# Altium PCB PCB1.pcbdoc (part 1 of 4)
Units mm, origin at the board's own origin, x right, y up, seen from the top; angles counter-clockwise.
Board outline 96.27 x 122.17 mm, 6 copper layers (Top Layer, Inner1, Inner2, Inner3, Inner4, Bottom Layer); 169 components, 166 nets, 787 pads, 477 vias.
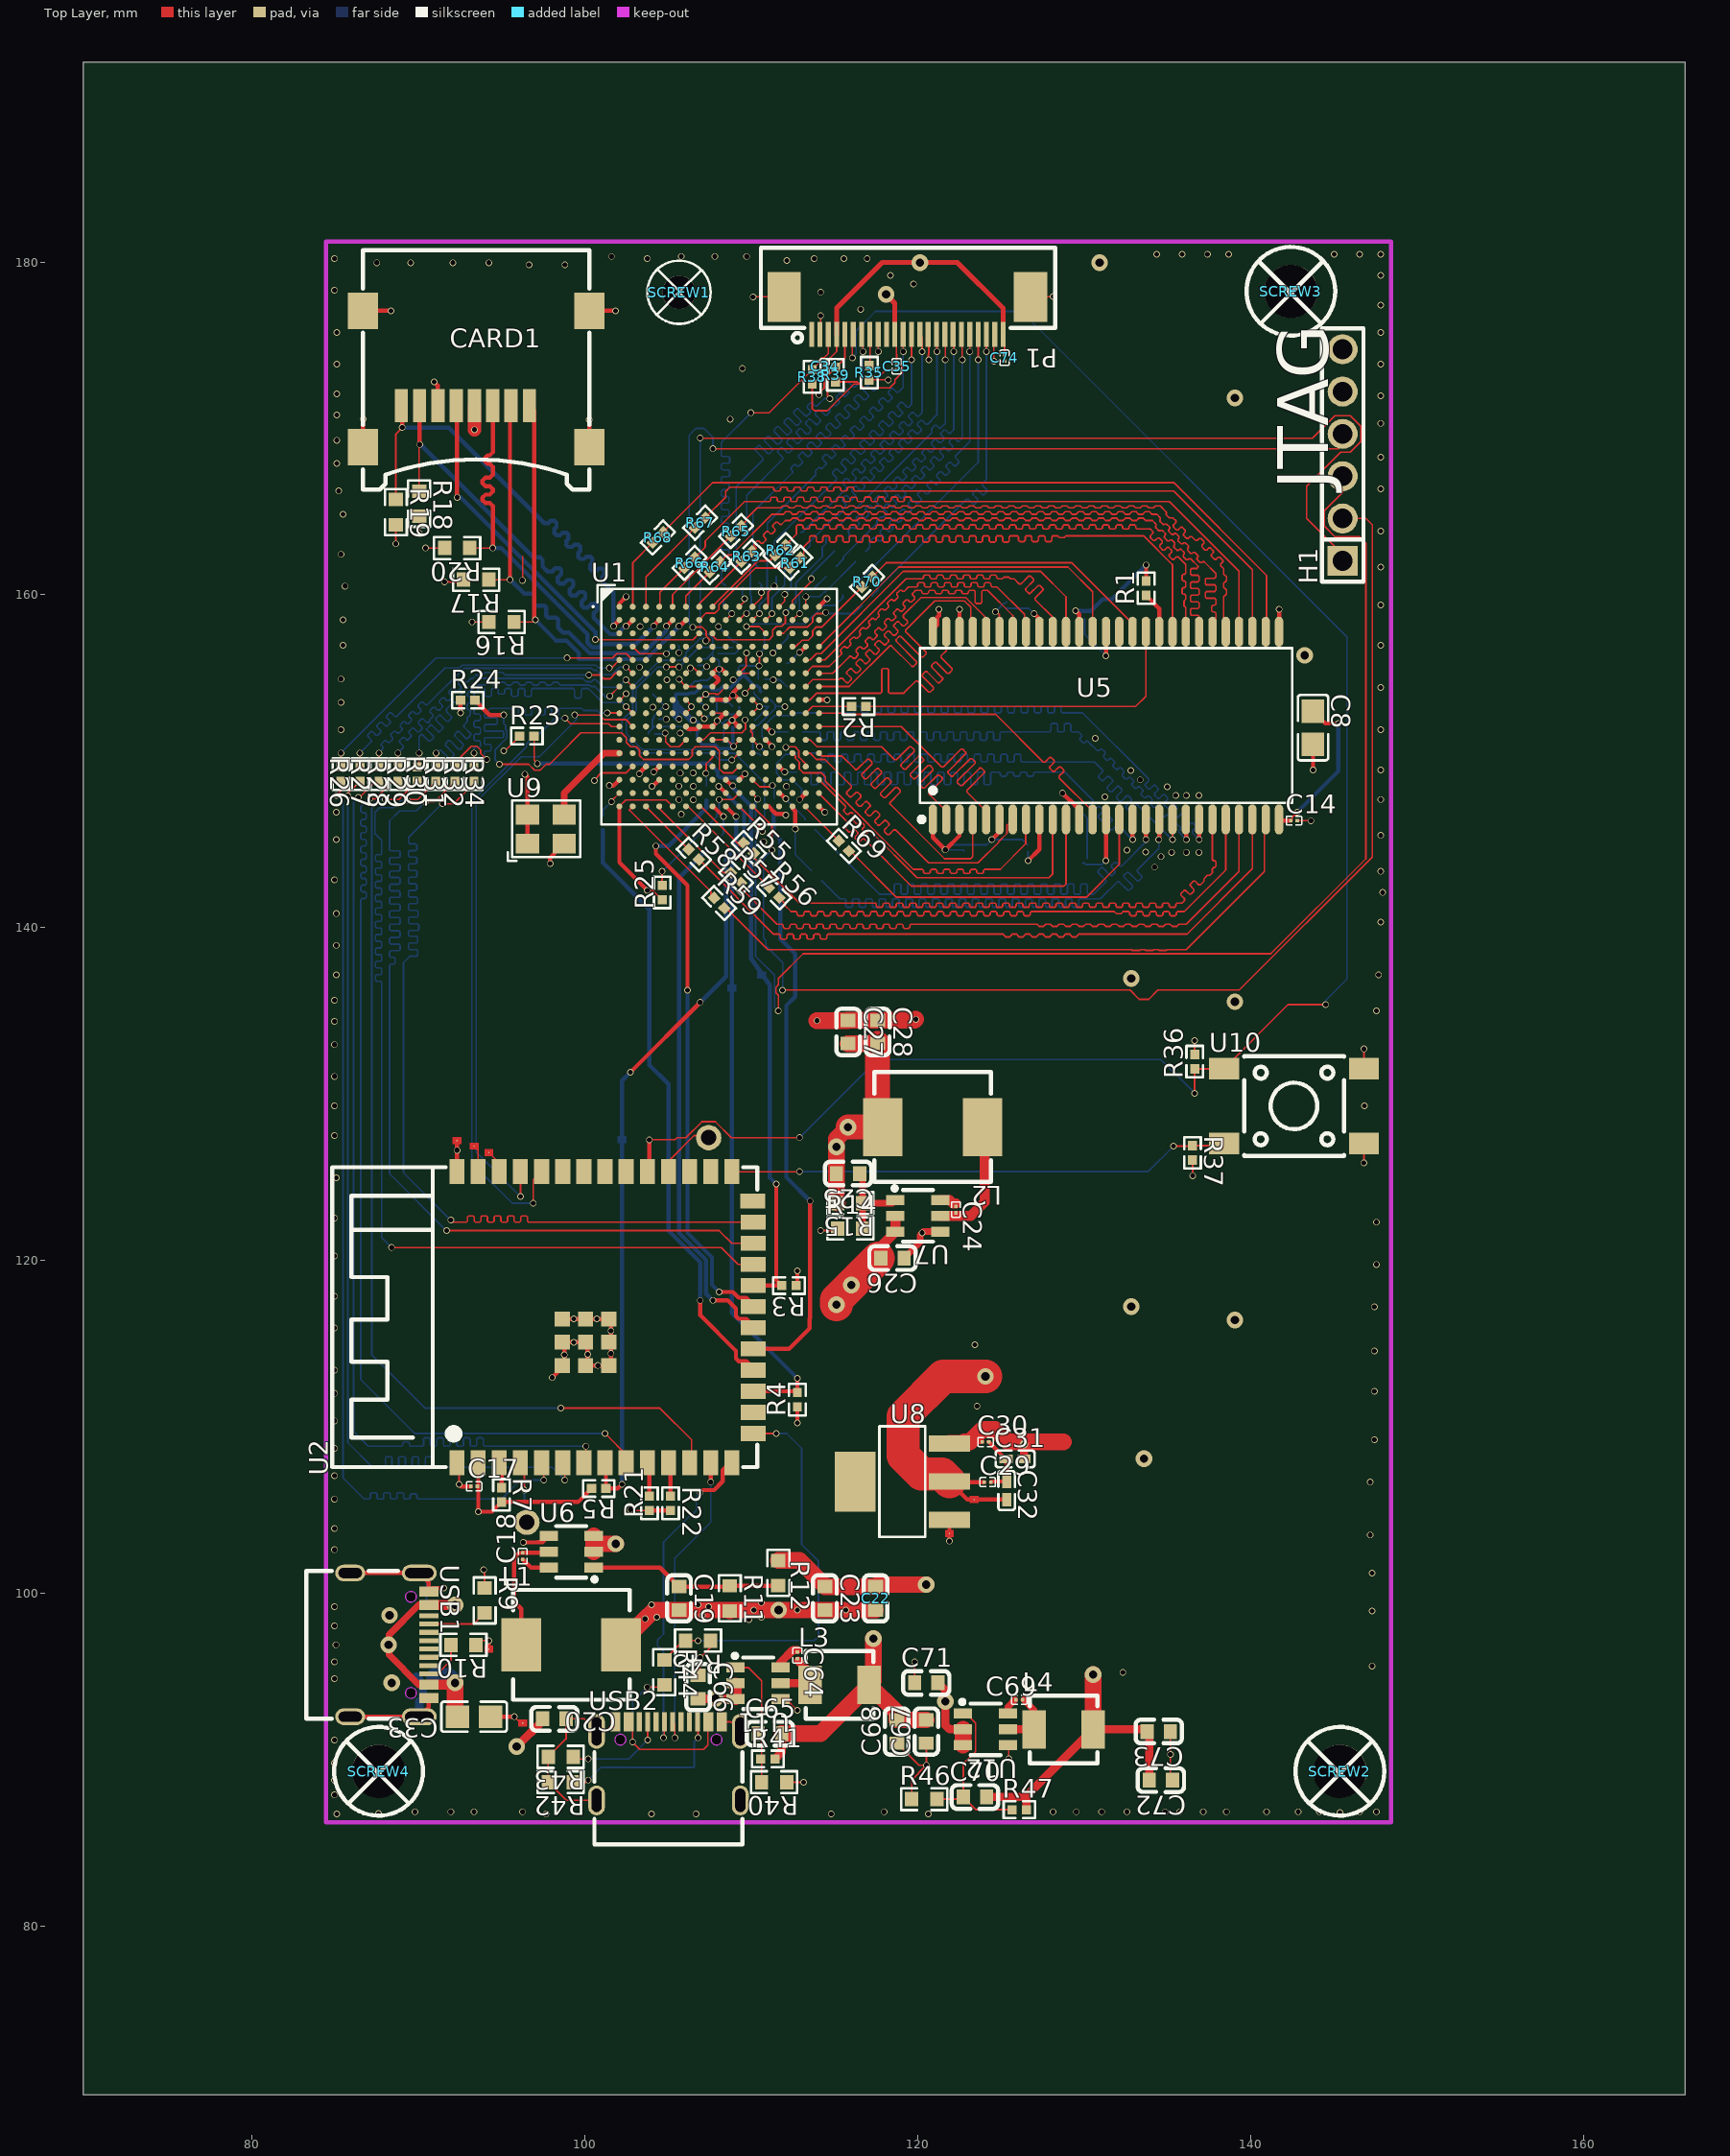
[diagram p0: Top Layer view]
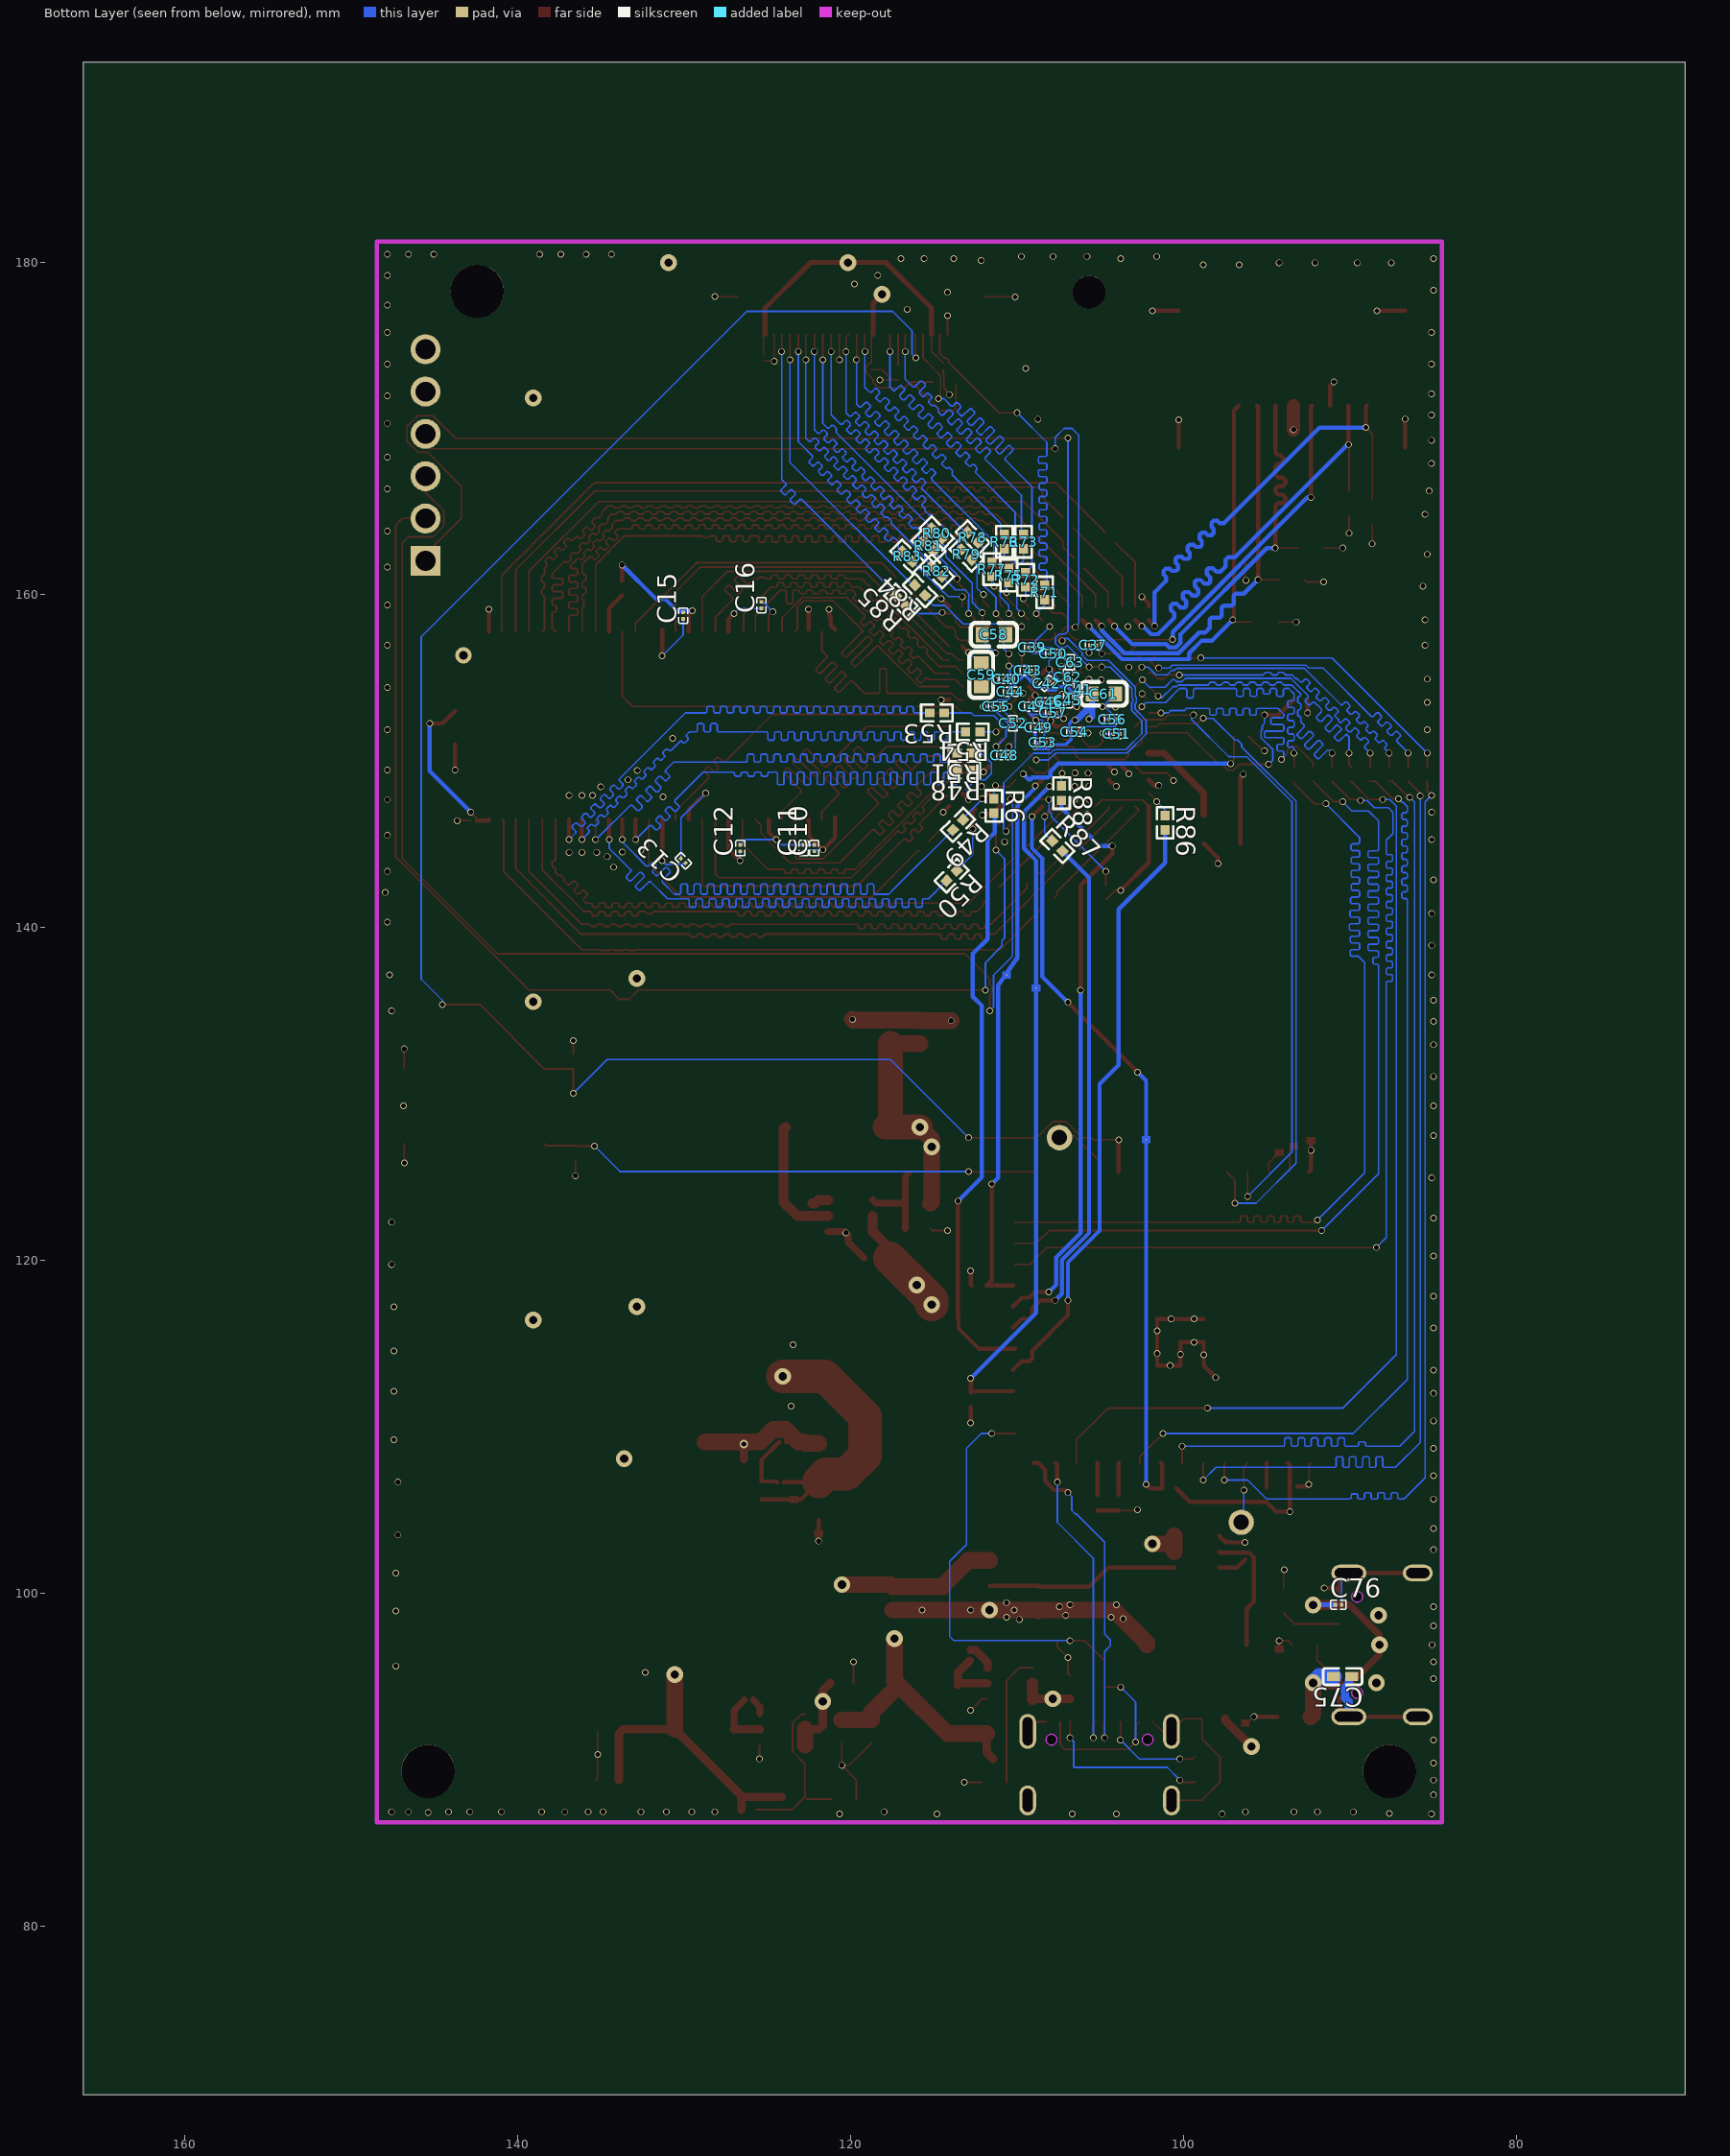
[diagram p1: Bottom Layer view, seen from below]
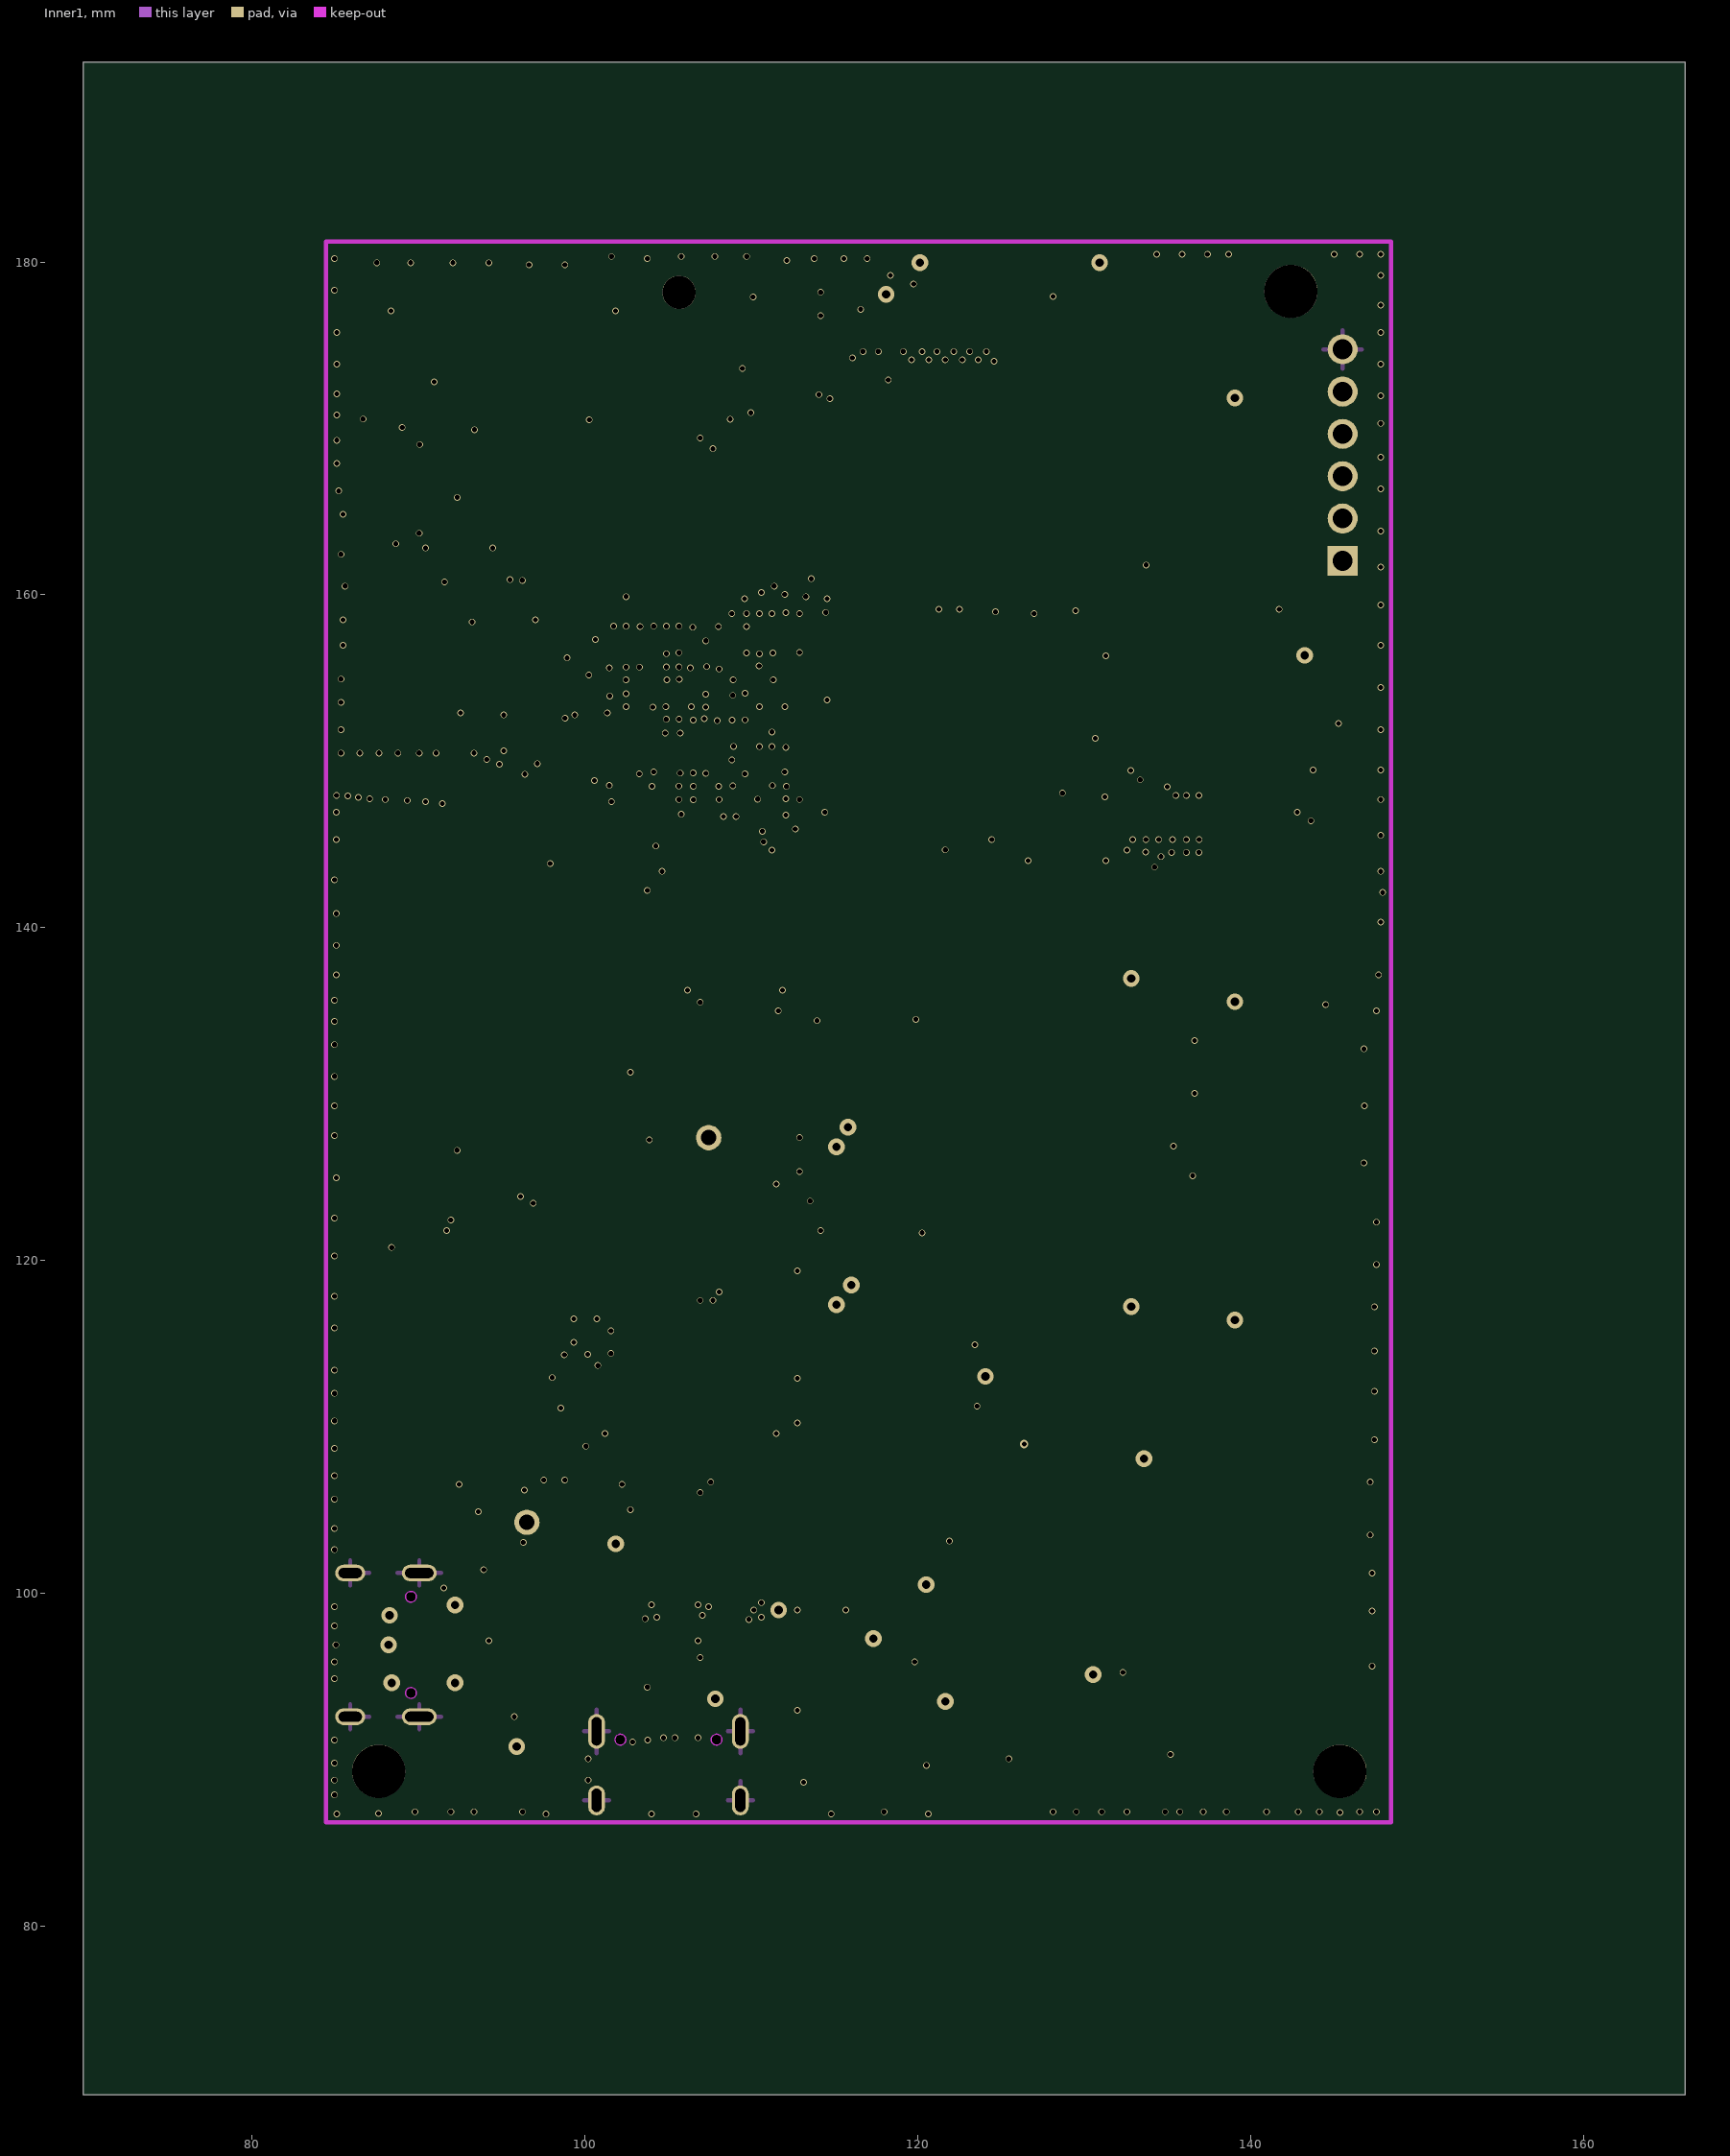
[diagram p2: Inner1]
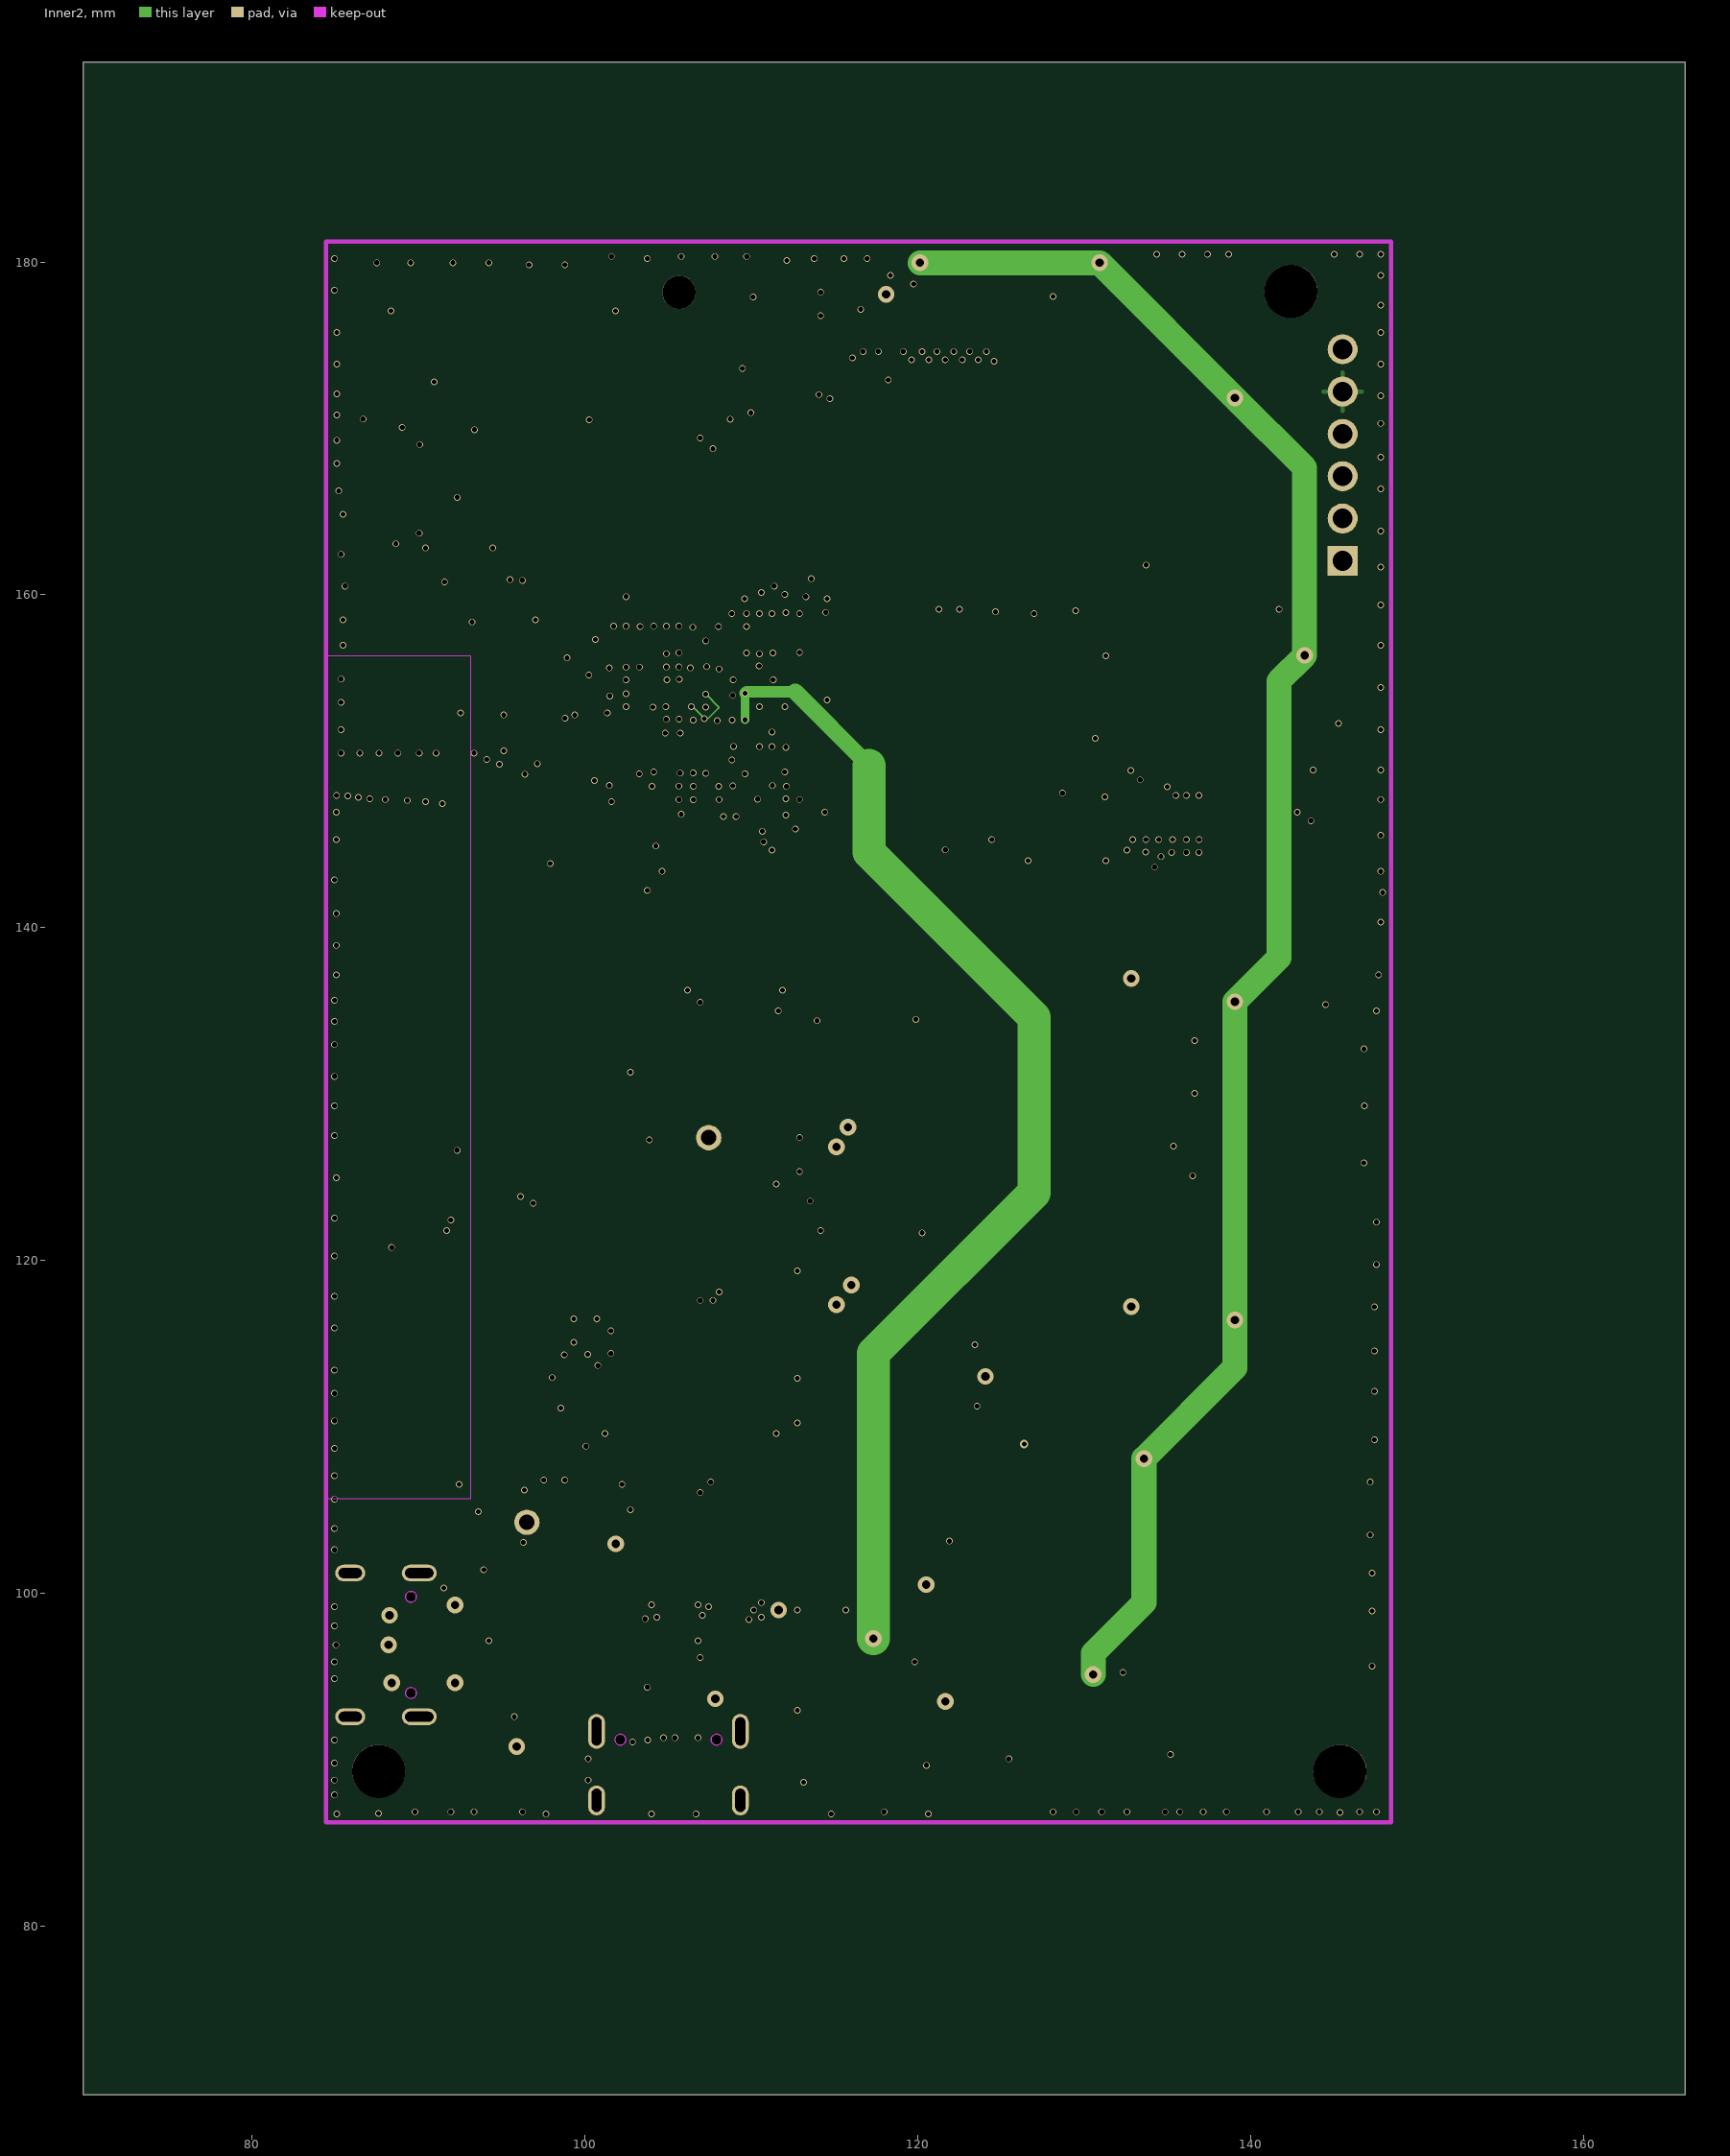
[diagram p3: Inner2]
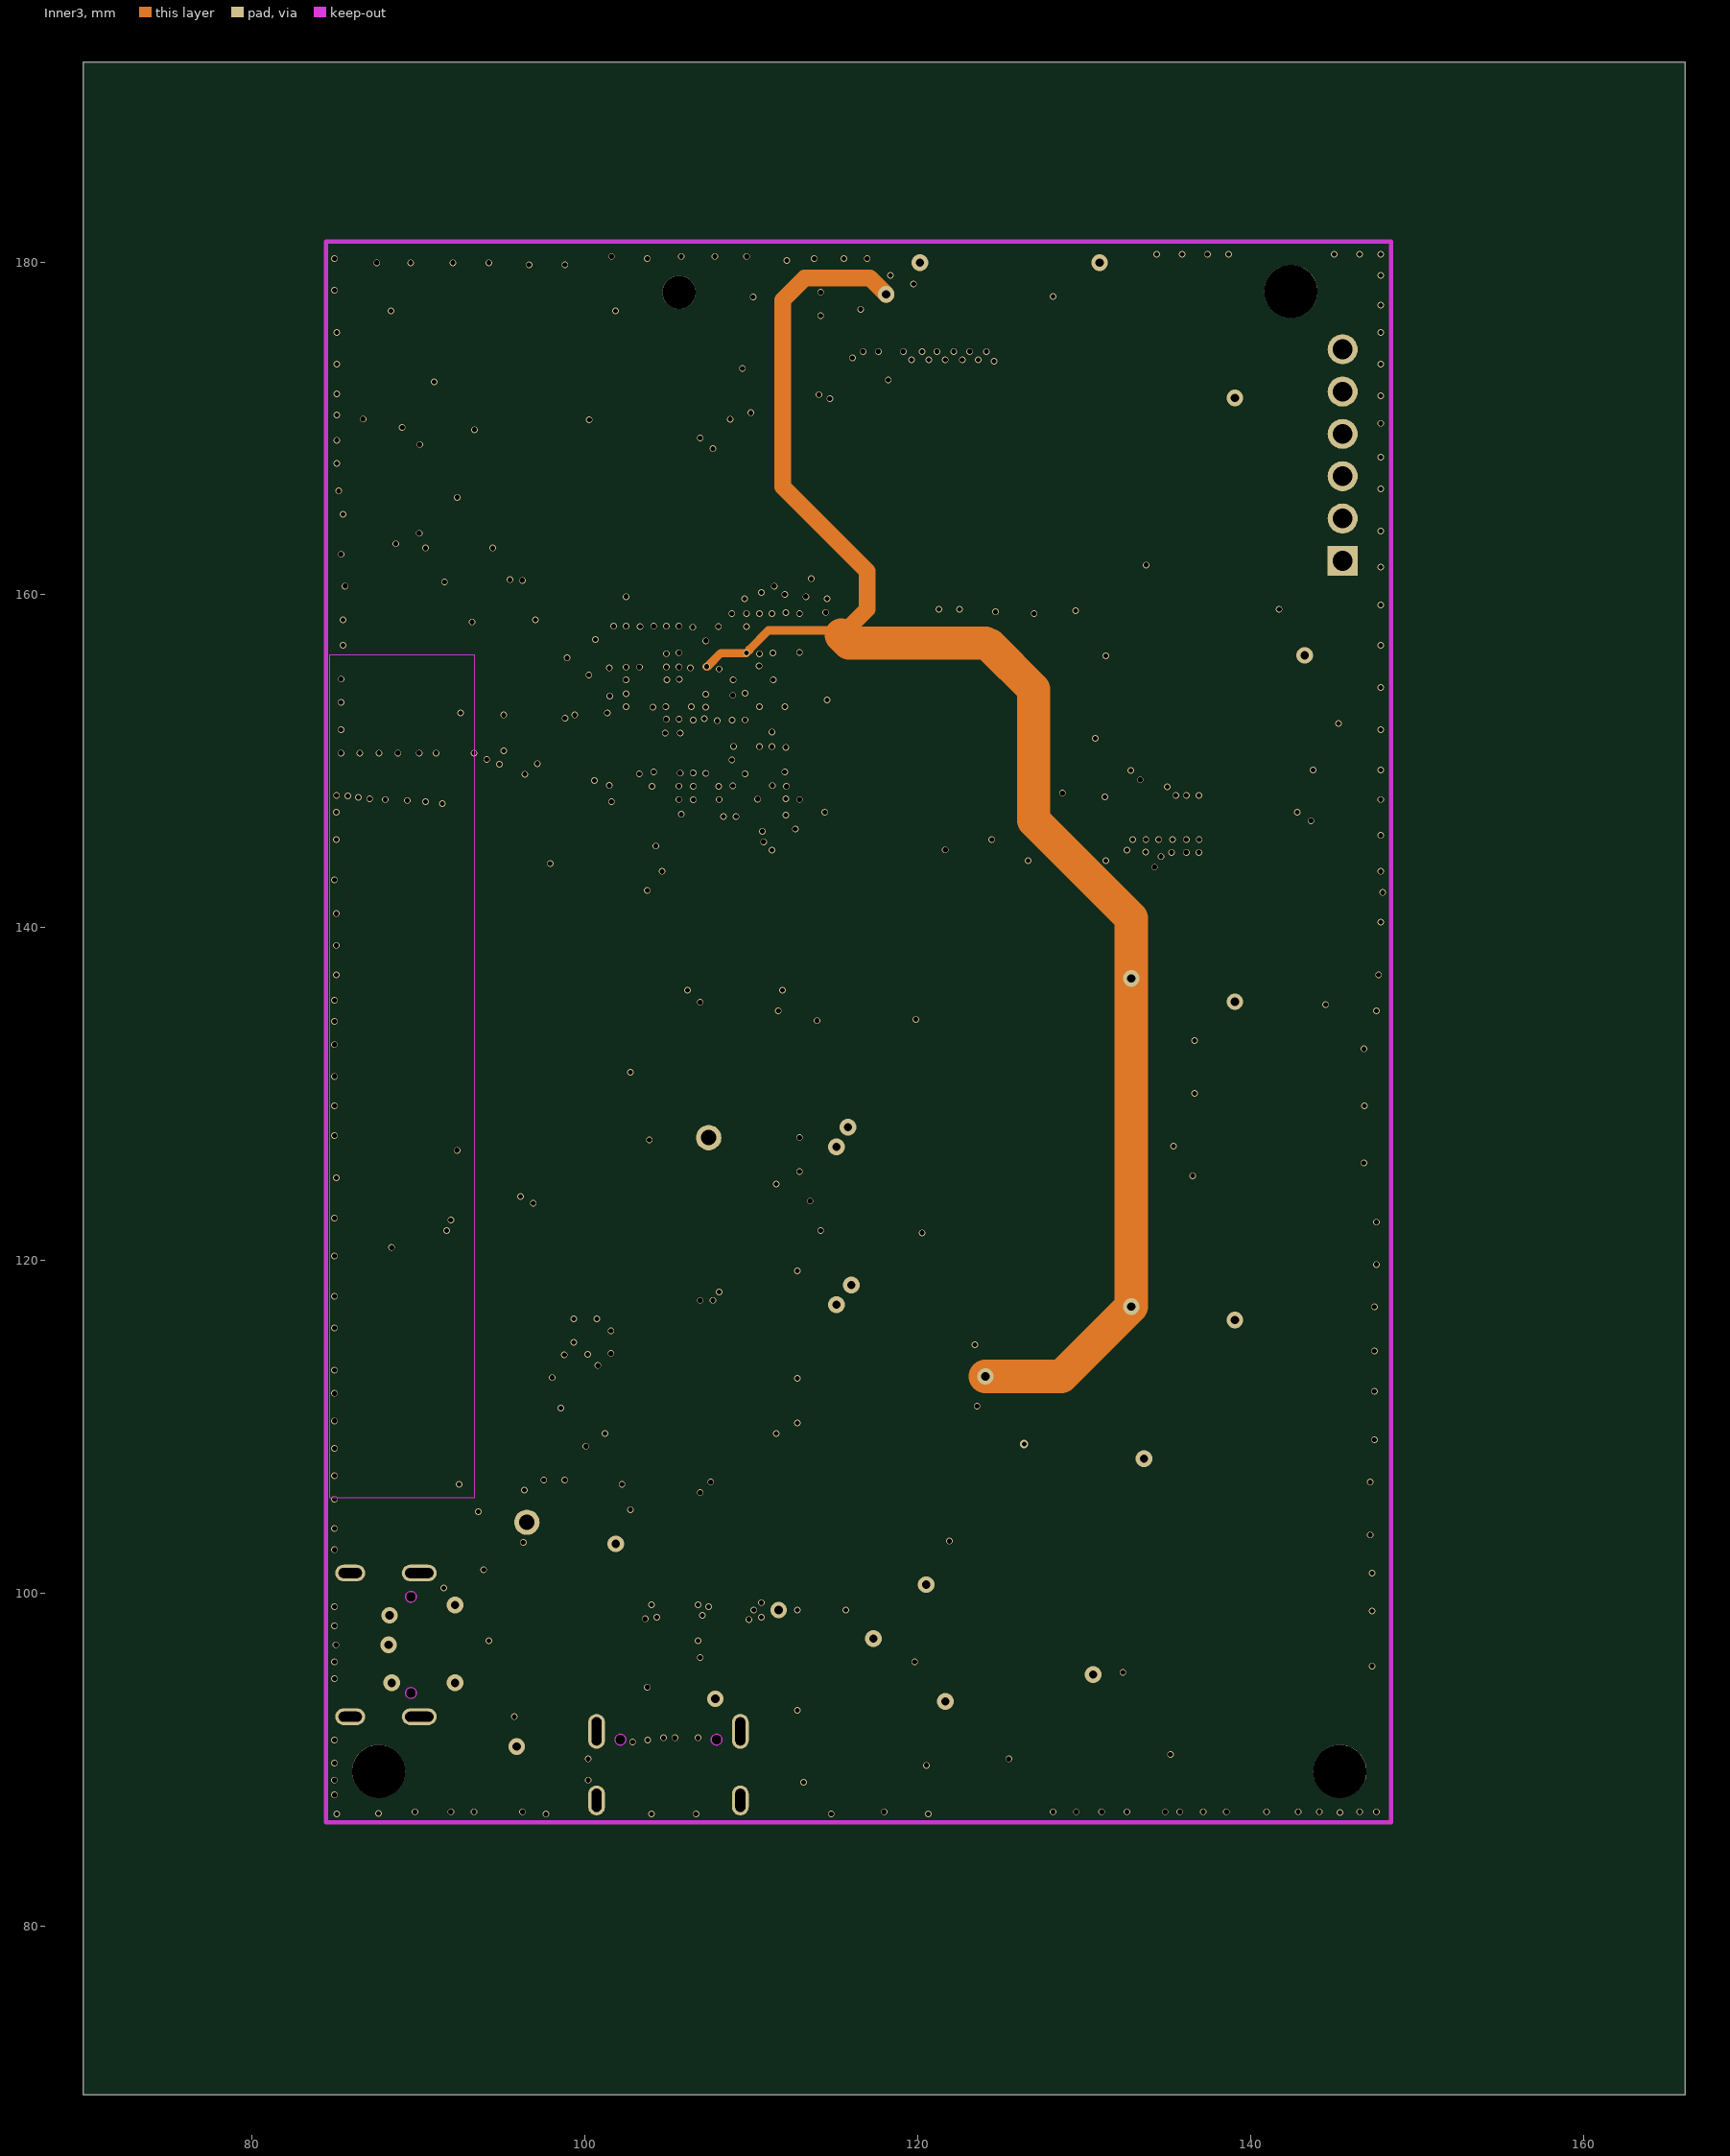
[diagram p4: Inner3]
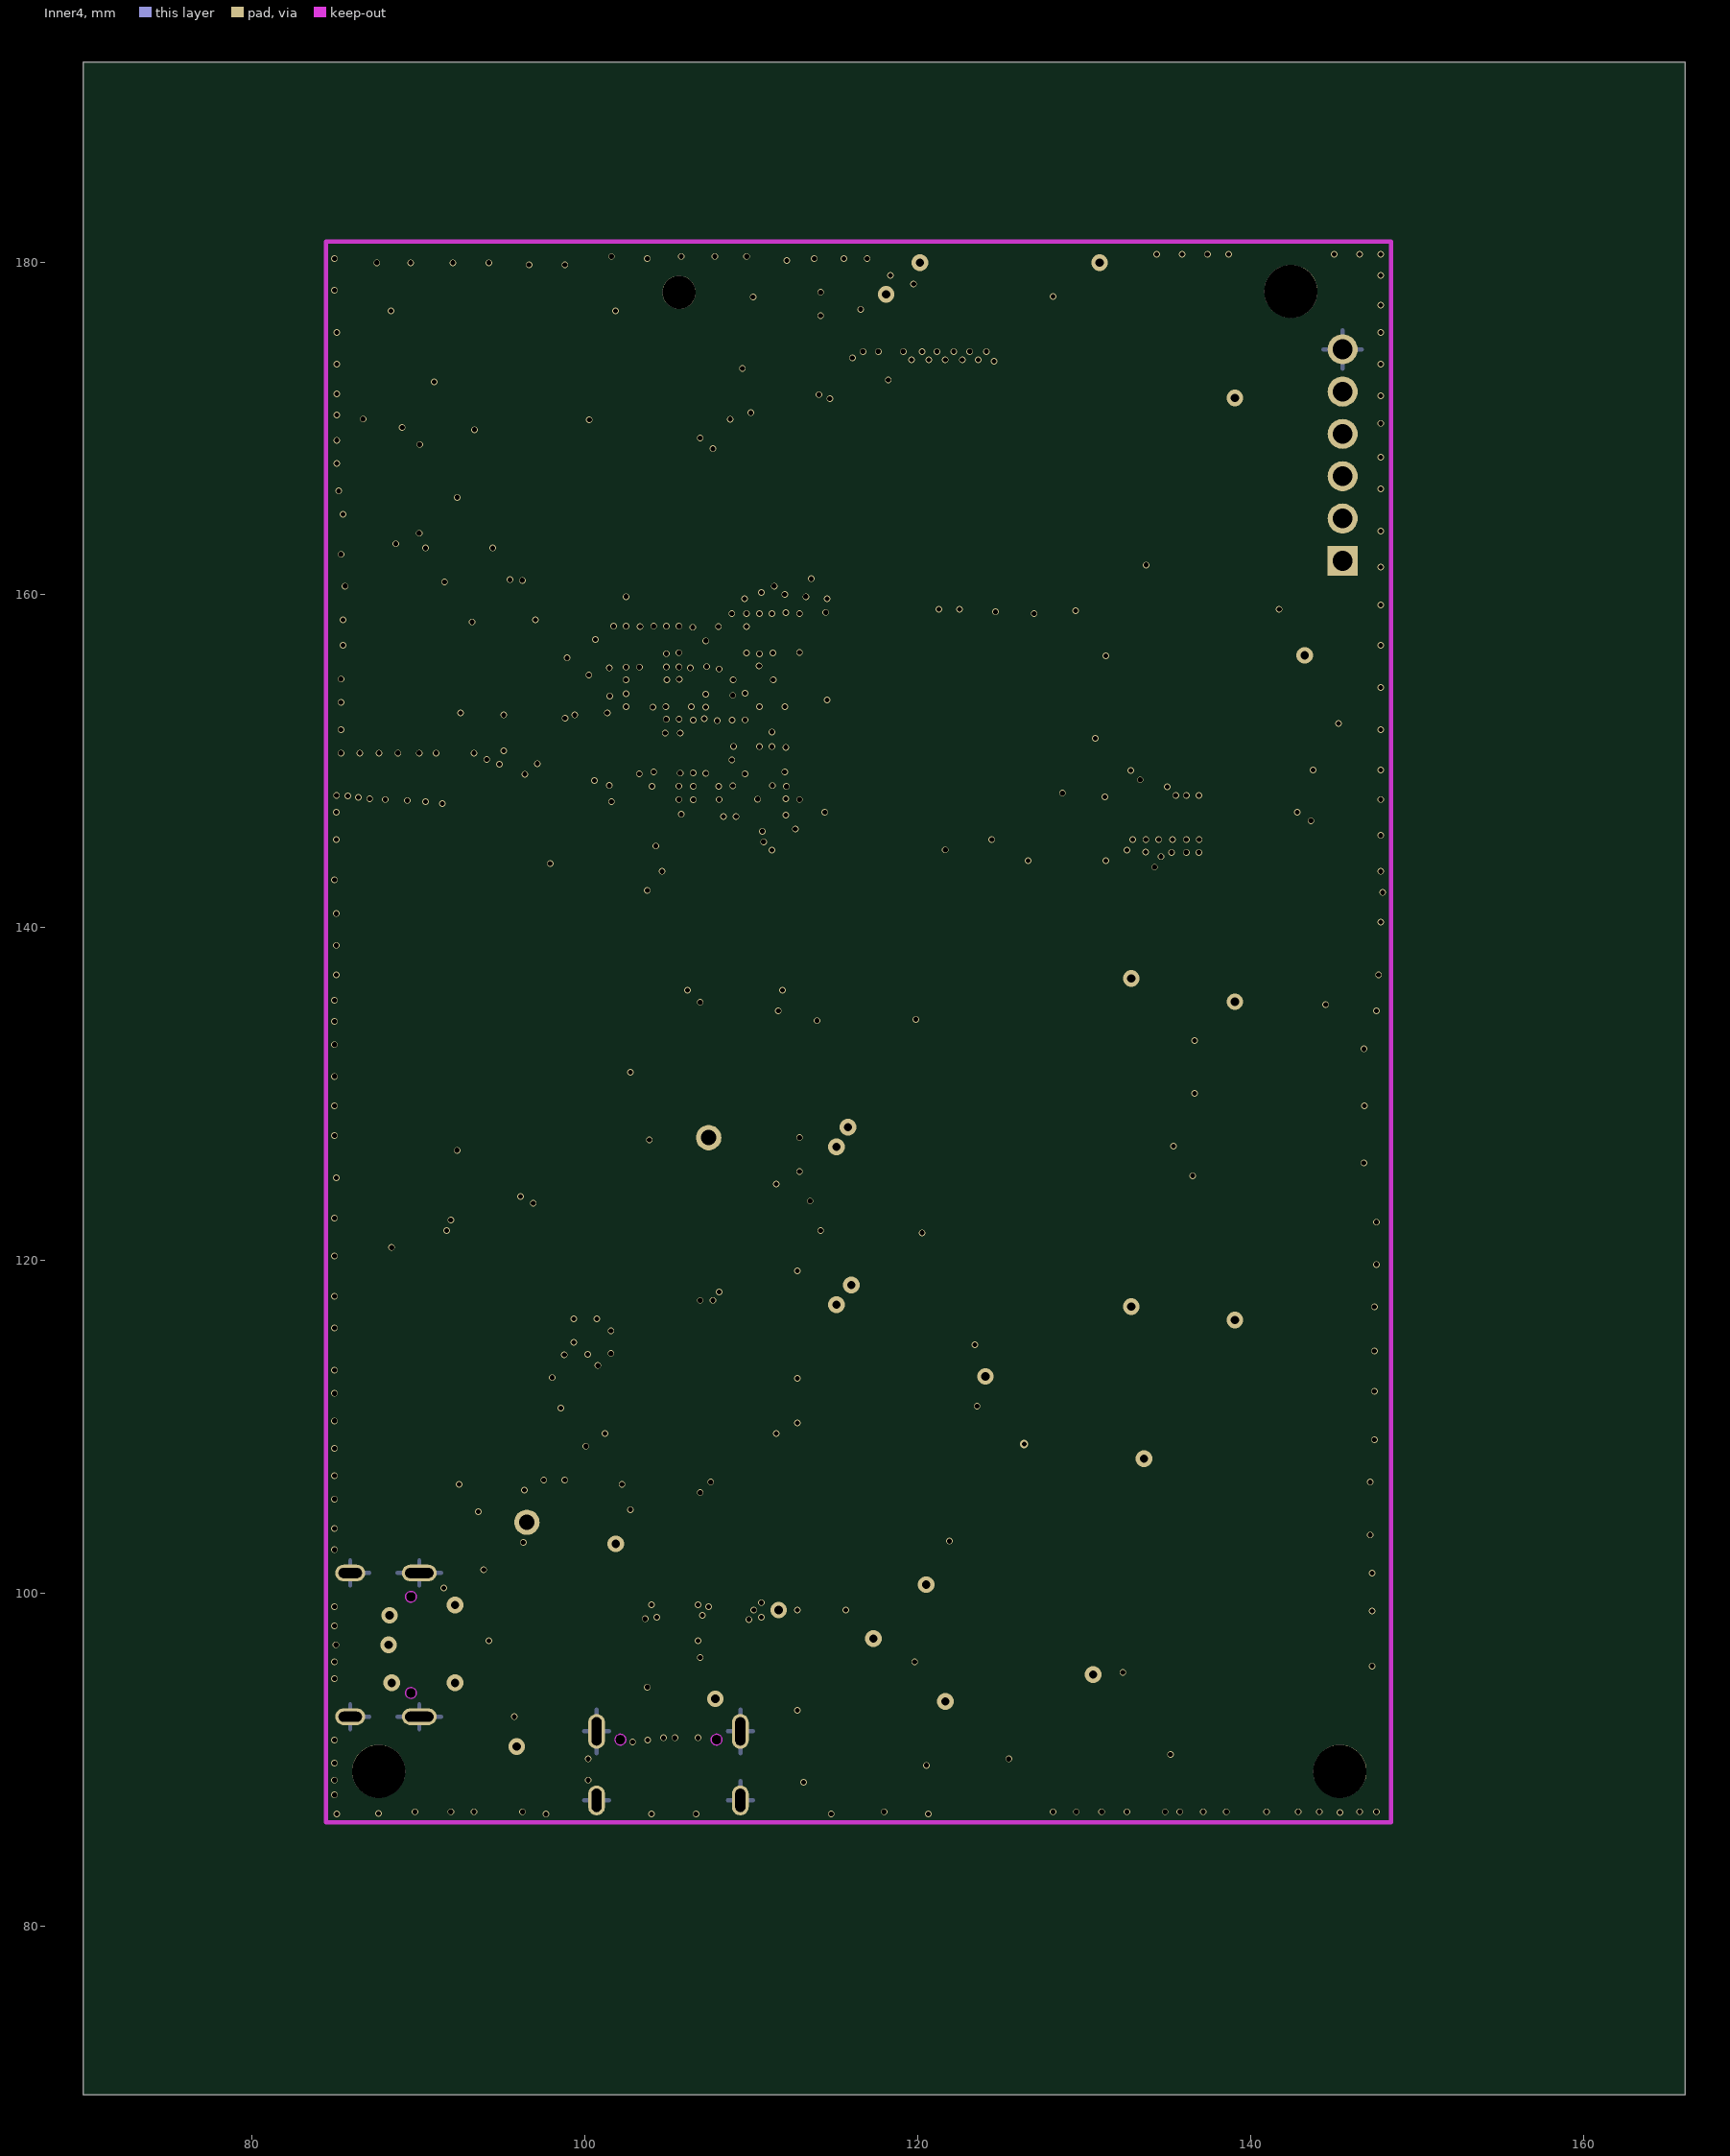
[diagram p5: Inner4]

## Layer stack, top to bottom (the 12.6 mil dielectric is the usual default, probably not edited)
Top Layer: signal copper (thickness not stored)
Dielectric: dielectric 0.32, FR-4, Dk 4.8
Inner1: signal copper (thickness not stored)
Dielectric: dielectric 0.32, FR-4, Dk 4.8
Inner2: signal copper (thickness not stored)
Dielectric: dielectric 0.32, FR-4, Dk 4.8
Inner3: signal copper (thickness not stored)
Dielectric: dielectric 0.32, FR-4, Dk 4.8
Inner4: signal copper (thickness not stored)
Dielectric: dielectric 0.32, FR-4, Dk 4.8
Bottom Layer: signal copper (thickness not stored)

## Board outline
166.116,69.85 69.85,69.85 69.85,192.024 166.116,192.024

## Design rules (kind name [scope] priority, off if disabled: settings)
BoardOutlineClearance copperThickness1oz [All] p0: genericclearance=0.254 ignorepadtopadclearanceinfootprint=FALSE except(0: Arc-SplitContinuation Track-SplitContinuation SMDPad-SplitContinuation THPad-SplitContinuation Via-SplitContinuation Fill-SplitContinuation Poly-SplitContinuation Region-SplitContinuation Text-SplitContinuation; 0.152: Track-CutoutEdge SMDPad-CutoutEdge THPad-CutoutEdge Via-CutoutEdge Region-CutoutEdge; 0.3: Track-OutlineEdge SMDPad-OutlineEdge THPad-OutlineEdge Via-OutlineEdge Fill-OutlineEdge Region-OutlineEdge Poly-OutlineEdge Text-OutlineEdge Fill-CutoutEdge)
BoardOutlineClearance copperThickness2oz [All] p0: genericclearance=0.254 ignorepadtopadclearanceinfootprint=FALSE except(0: Arc-SplitContinuation Track-SplitContinuation SMDPad-SplitContinuation THPad-SplitContinuation Via-SplitContinuation Fill-SplitContinuation Poly-SplitContinuation Region-SplitContinuation Text-SplitContinuation; 0.152: Track-CutoutEdge SMDPad-CutoutEdge THPad-CutoutEdge Via-CutoutEdge Region-CutoutEdge; 0.3: Track-OutlineEdge SMDPad-OutlineEdge THPad-OutlineEdge Via-OutlineEdge Fill-OutlineEdge Region-OutlineEdge Poly-OutlineEdge Text-OutlineEdge Fill-CutoutEdge)
Clearance copperThickness1oz [(InNet('SD_A0') OR InNet('SD_A1') OR InNet('SD_A2') OR InNet('SD_A3') OR InNet('SD_A4') OR InNet('SD_A5') OR InNet('SD_A6') OR InNet('SD_A7') OR InNet('SD_A8') OR InNet('SD_A9') OR InNet('SD_A10') OR InNet('SD_A11') OR InNet('SD_A12') OR InNet('SD_DQ15') OR InNet('SD_DQ14') OR InNet('SD_DQ8') OR InNet('SD_BA0') OR InNet('SD_BA1') OR InNet('SD_DQ9') OR InNet('SD_DQ7') OR InNet('SD_CLK') OR InNet('SD_WE_N') OR InNet('SD_DQ10') OR InNet('SD_CAS_N') OR InNet('SD_DQM1') OR InNet('SD_DQ2') OR InNet('SD_DQ3') OR InNet('SD_DQ11') OR InNet('SD_DQ12') OR InNet('SD_DQ13') OR InNet('SD_DQ0') OR InNet('SD_DQ1') OR InNet('SD_CS_N') OR InNet('SD_RAS_N') OR InNet('SD_DQ4') OR InNet('SD_DQ6') OR InNet('GND') OR InNet('SD_DQ5') OR InNet('SD_DQM0') OR InNet('$1N9437') OR InNet('+3V3') OR InNet('$1N11348') OR InNet('DOUT') OR InNet('DIN') OR InNet('CCLK') OR InNet('DONE') OR InNet('PROGRAMN') OR InNet('INITN') OR InNet('$1N11975') OR InNet('DN') OR InNet('DP') OR InNet('$1N14459') OR InNet('$1N14416') OR InNet('$1N14567') OR InNet('+5V') OR InNet('$1N16833') OR InNet('$1N16832') OR InNet('+1V1') OR InNet('$1N16834') OR InNet('+1V8') OR InNet('$1N17349') OR InNet('$1N12557') OR InNet('$1N12553') OR InNet('M_D2') OR InNet('M_D3') OR InNet('M_CMD') OR InNet('M_CLK') OR InNet('M_D0') OR InNet('M_D1') OR InNet('SDA') OR InNet('SCL') OR InNet('RESET') OR InNet('VSYNC') OR InNet('HREF') OR InNet('Y9') OR InNet('MCLK') OR InNet('Y8') OR InNet('Y7') OR InNet('PCLK') OR InNet('Y6') OR InNet('Y2') OR InNet('Y5') OR InNet('Y3') OR InNet('Y4') OR InNet('CRYSTAL') OR InNet('SSPI_CS_N') OR InNet('D0') OR InNet('D1') OR InNet('D2') OR InNet('D4') OR InNet('D3') OR InNet('D5') OR InNet('D6') OR InNet('D7') OR InNet('RX') OR InNet('TX') OR InNet('$1N29790') OR InNet('$1N29833') OR InNet('$1N29916') OR InNet('$1N29959') OR InNet('$1N30002') OR InNet('$1N30085') OR InNet('$1N30089') OR InNet('$1N30093') OR InNet('TDO') OR InNet('TDI') OR InNet('TMS') OR InNet('TCK') OR InNet('PROGRAM') OR InNet('$2N5507') OR InNet('$2N5509') OR InNet('$2N5511') OR InNet('FSDA') OR InNet('FSCL') OR InNet('+2V5') OR InNet('$1N60668') OR InNet('$1N60669') OR InNet('$1N60670') OR InNet('USB_VBUS') OR InNet('$1N63772') OR InNet('$1N63749') OR InNet('$1N63825') OR InNet('+2V8') OR InNet('$1N64402') OR InNet('$1N64401') OR InNet('$1N64403') OR InNet('$1N71242') OR InNet('$1N71285') OR InNet('$1N71328') OR InNet('$1N71371') OR InNet('$1N71500') OR InNet('$1N71457') OR InNet('$1N74645') OR InNet('$1N74688') OR InNet('$1N74731') OR InNet('$1N74774') OR InNet('$1N74817') OR InNet('$1N74931') OR InNet('$1N74974') OR InNet('$1N75017') OR InNet('$1N75060') OR InNet('$1N75103') OR InNet('$1N75146') OR InNet('$1N75189') OR InNet('$1N75232') OR InNet('$1N75310') OR InNet('$1N75353') OR InNet('$1N78998') OR InNet('$1N79086') OR InNet('$1N79129') OR InNet('$1N79172') OR InNet('$1N79215') OR InNet('$1N79258') OR InNet('$1N79301') OR InNet('$1N79344') OR InNet('$1N79387') OR InNet('$1N79430') OR InNet('$1N79473') OR InNet('$1N79516') OR InNet('$1N79046') OR InNet('$1N79529') OR InNet('$1N79537') OR InNet('$1N79556') OR InNet('$1N79602') OR InNet('$1N79645') OR InNet('$1N79688'))] p1: gap=0.178 ignorepadtopadclearanceinfootprint=FALSE except(0.099: Track-Track; 0.152: Track-SMDPad SMDPad-SMDPad Track-THPad SMDPad-THPad THPad-THPad Track-Via SMDPad-Via THPad-Via Via-Via SMDPad-Fill THPad-Fill Via-Fill Fill-Fill Track-Region SMDPad-Region THPad-Region Via-Region Region-Region Track-Poly SMDPad-Poly THPad-Poly Via-Poly Fill-Poly Region-Poly Poly-Poly Track-Text SMDPad-Text THPad-Text Via-Text Fill-Text Region-Text Poly-Text Text-Text; 0.175: Track-Hole SMDPad-Hole THPad-Hole Via-Hole Fill-Hole Region-Hole Poly-Hole Text-Hole Sheet-Hole; 0.3: Track-Fill Fill-Region Track-Sheet SMDPad-Sheet THPad-Sheet Via-Sheet Fill-Sheet Region-Sheet Poly-Sheet Text-Sheet)
Clearance copperThickness2oz [All] p1: gap=0.178 ignorepadtopadclearanceinfootprint=FALSE except(0.152: Track-SMDPad SMDPad-SMDPad Track-THPad SMDPad-THPad THPad-THPad Track-Via SMDPad-Via THPad-Via Via-Via SMDPad-Fill THPad-Fill Via-Fill Fill-Fill Track-Region SMDPad-Region THPad-Region Via-Region Region-Region Track-Poly SMDPad-Poly THPad-Poly Via-Poly Fill-Poly Region-Poly Poly-Poly Track-Text SMDPad-Text THPad-Text Via-Text Fill-Text Region-Text Poly-Text Text-Text; 0.175: Track-Hole SMDPad-Hole THPad-Hole Via-Hole Fill-Hole Region-Hole Poly-Hole Text-Hole Sheet-Hole; 0.203: Track-Track; 0.3: Track-Fill Fill-Region Track-Sheet SMDPad-Sheet THPad-Sheet Via-Sheet Fill-Sheet Region-Sheet Poly-Sheet Text-Sheet)
DiffPairsRouting differentialPair [All] p1: maxuncoupledlength=10 minlimit=6 maxlimit=6 mostfreqgap=6 toplayer_minwidth=5 toplayer_prefwidth=10 toplayer_maxwidth=100 bottomlayer_minwidth=5 bottomlayer_prefwidth=10 bottomlayer_maxwidth=100 midlayer1_minwidth=5 midlayer1_prefwidth=10 midlayer1_maxwidth=100 midlayer2_minwidth=5 midlayer2_prefwidth=10 midlayer2_maxwidth=100 midlayer3_minwidth=5 midlayer3_prefwidth=10 midlayer3_maxwidth=100 midlayer4_minwidth=5 midlayer4_prefwidth=10 midlayer4_maxwidth=100
PasteMaskExpansion pasteMaskExpansion [All] p1: expansion=0
PlaneConnect innerPlane [All] p1: planeconnectstyle=Relief reliefexpansion=0.508 reliefentries=4 reliefconductorwidth=0.254 reliefairgap=0.254
PolygonConnect copperRegion [All] p1: connectstyle=Relief reliefentries=4 reliefconductorwidth=10 polygonreliefangle="90 Angle" airgapwidth=10
RoutingVias viaSize [All] p1: viastyle="Through Hole" holewidth=11.811 minholewidth=11.811 maxholewidth=248.0314 width=15.748 minwidth=15.748 maxwidth=393.7008
SolderMaskExpansion solderMaskExpansion [All] p1: useseparateexpansions=TRUE expansion=2 expansionbottom=2
Width copperThickness1oz [All] p1: maxlimit=100 minlimit=4 preferedwidth=4
Width copperThickness2oz [All] p1: maxlimit=100 minlimit=8 preferedwidth=10

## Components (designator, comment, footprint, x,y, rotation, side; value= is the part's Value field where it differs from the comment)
C8 "CL21A476MQYNNNE" C0805 143.764,152.019 r270 top
C10 "GRM022R60J104KE15D" C01005 122.174,144.78 r90 bottom
C11 "GRM022R60J104KE15D" C01005 122.809,144.78 r90 bottom
C12 "GRM022R60J104KE15D" C01005 126.619,144.78 r90 bottom
C13 "GRM022R60J104KE15D" C01005 130.048,144.018 r45 bottom
C14 "GRM022R60J104KE15D" C01005 142.621,146.431 r0 top
C15 "GRM022R60J104KE15D" C01005 130.048,158.75 r90 bottom
C16 "GRM022R60J104KE15D" C01005 125.349,159.385 r90 bottom
C17 "GRM022R60J104KE15D" C01005 93.345,106.426 r0 top
C18 "GRM022R60J104KE15D" C01005 96.266,102.235 r90 top
C19 "TCC0603X7R104K500CT" C0603 105.664,99.695 r270 top
C20 "TCC0603X5R226M6R3CT" C0603 98.171,92.456 r180 top
C22 "TCC0603X5R226M6R3CT" C0603 117.475,99.695 r270 top
C23 "TCC0603X5R226M6R3CT" C0603 114.427,99.695 r270 top
C24 "GRM022R60J104KE15D" C01005 122.301,123.063 r270 top
C25 "TCC0603X7R104K500CT" C0603 115.824,125.222 r180 top
C26 "TCC0603X5R226M6R3CT" C0603 118.491,120.142 r180 top
C27 "TCC0603X5R226M6R3CT" C0603 115.824,133.731 r270 top
C28 "TCC0603X5R226M6R3CT" C0603 117.602,133.731 r270 top
C29 "GRM022R60J104KE15D" C01005 124.206,106.68 r0 top
C30 "GRM022R60J104KE15D" C01005 124.079,109.093 r0 top
C31 "GRM155R60J106ME44D" C0402 125.857,108.077 r0 top
C32 "GRM155R60J106ME44D" C0402 125.349,106.172 r270 top
C33 "CL21A476MQYNNNE" C0805 93.345,92.583 r180 top
C34 "GRM022R60J104KE15D" C01005 114.427,173.736 r270 top
C35 "GRM022R60J104KE15D" C01005 118.745,173.736 r270 top
C37 "GRM022R60J104KE15D" C01005 105.41,156.972 r180 bottom
C39 "GRM022R60J104KE15D" C01005 109.093,156.845 r180 bottom
C40 "GRM022R60J104KE15D" C01005 110.617,154.94 r180 bottom
C41 "GRM022R60J104KE15D" C01005 106.299,154.305 r90 bottom
C42 "GRM022R60J104KE15D" C01005 108.204,154.686 r135 bottom
C43 "GRM022R60J104KE15D" C01005 109.347,155.448 r180 bottom
C44 "GRM022R60J104KE15D" C01005 110.363,154.178 r180 bottom
C45 "GRM022R60J104KE15D" C01005 106.934,153.67 r270 bottom
C46 "GRM022R60J104KE15D" C01005 108.077,153.543 r180 bottom
C47 "GRM022R60J104KE15D" C01005 109.093,153.289 r0 bottom
C48 "GRM022R60J104KE15D" C01005 110.744,150.368 r180 bottom
C49 "GRM022R60J104KE15D" C01005 108.712,152.019 r180 bottom
C50 "GRM022R60J104KE15D" C01005 107.823,156.464 r180 bottom
C51 "GRM022R60J104KE15D" C01005 104.013,151.638 r180 bottom
C52 "GRM022R60J104KE15D" C01005 110.236,152.273 r270 bottom
C53 "GRM022R60J104KE15D" C01005 108.458,151.13 r180 bottom
C54 "GRM022R60J104KE15D" C01005 106.553,151.765 r180 bottom
C55 "GRM022R60J104KE15D" C01005 111.252,153.289 r0 bottom
C56 "GRM022R60J104KE15D" C01005 104.267,152.527 r180 bottom
C57 "GRM022R60J104KE15D" C01005 107.823,152.908 r0 bottom
C58 "TCC0603X5R226M6R3CT" C0603 111.379,157.607 r180 bottom
C59 "TCC0603X5R226M6R3CT" C0603 112.141,155.194 r90 bottom
C61 "TCC0603X5R226M6R3CT" C0603 104.775,154.051 r180 bottom
C62 "GRM022R60J104KE15D" C01005 106.934,155.067 r270 bottom
C63 "GRM022R60J104KE15D" C01005 106.807,155.956 r90 bottom
C64 "GRM022R60J104KE15D" C01005 112.776,96.266 r270 top
C65 "TCC0603X7R104K500CT" C0603 111.125,91.567 r0 top
C66 "TCC0603X5R226M6R3CT" C0603 106.807,94.361 r270 top
C67 "TCC0603X5R226M6R3CT" C0603 120.523,91.694 r90 top
C68 "TCC0603X5R226M6R3CT" C0603 118.745,91.694 r90 top
C69 "GRM022R60J104KE15D" C01005 126.111,93.599 r0 top
C70 "TCC0603X7R104K500CT" C0603 123.444,87.757 r0 top
C71 "TCC0603X5R226M6R3CT" C0603 120.523,94.615 r0 top
C72 "TCC0603X5R226M6R3CT" C0603 134.62,88.773 r180 top
C73 "TCC0603X5R226M6R3CT" C0603 134.493,91.694 r180 top
C74 "GRM022R60J104KE15D" C01005 125.222,174.244 r270 top
C75 "GRM155R60J106ME44D" C0402 90.424,94.996 r0 bottom
C76 "GRM022R60J104KE15D" C01005 90.678,99.314 r180 bottom
CARD1 "DS1139-06-08SS4BSR" TF-SMD_DS1139-06-08SS4BSR 93.472,172.974 r0 top
H1 "2.54-1x6P直针" HDR-TH_6P-P2.54-V-M-1 145.542,168.402 r90 top
L1 "FXL0630-6R8-M" IND-SMD_L7.0-W6.6 99.187,96.901 r0 top
L2 "FXL0630-100-M" IND-SMD_L7.3-W6.8 120.904,128.016 r180 top
L3 "SL0420-3R3M" IND-SMD_L4.5-W4.1_SL0420 115.316,94.488 r0 top
L4 "SL0420-3R3M" IND-SMD_L4.5-W4.1_SL0420 128.778,91.821 r0 top
P1 "AFC07-S24FCC-00" FPC-SMD_AFC07-S24FCC-00 119.38,176.784 r180 top
R1 "0402WGF1002TCE" R0402 133.731,160.401 r90 top
R2 "0402WGF330JTCE" R0402 116.459,153.289 r180 top
R3 "0402WGF1002TCE" R0402 112.268,118.491 r180 top
R4 "0402WGF1002TCE" R0402 112.776,111.633 r90 top
R5 "0402WGF1002TCE" R0402 100.838,106.299 r180 top
R6 "0402WGF330JTCE" R0402 111.379,147.32 r270 bottom
R7 "0402WGF1002TCE" R0402 94.996,105.918 r270 top
R9 "0603WAF5101T5E" R0603 93.98,99.568 r270 top
R10 "0603WAF5101T5E" R0603 92.71,96.901 r180 top
R11 "FRC0603F1963TS" R0603 108.712,99.695 r270 top
R12 "FRC0603F6202TS" R0603 111.633,101.219 r270 top
R14 "FRC0603F6202TS" R0603 115.951,121.92 r0 top
R15 "0603WAF2322T5E" R0603 115.951,123.444 r180 top
R16 "FRC0603F6202TS" R0603 94.996,158.369 r180 top
R17 "FRC0603F6202TS" R0603 93.472,160.909 r180 top
R18 "FRC0603F6202TS" R0603 90.043,165.481 r270 top
R19 "FRC0603F6202TS" R0603 88.646,164.973 r270 top
R20 "FRC0603F6202TS" R0603 92.329,162.814 r180 top
R21 "0402WGF1002TCE" R0402 103.886,105.41 r270 top
R22 "0402WGF1002TCE" R0402 105.156,105.41 r270 top
R23 "0402WGF1002TCE" R0402 96.52,151.511 r0 top
R24 "0402WGF1002TCE" R0402 92.964,153.67 r0 top
R25 "0402WGF1002TCE" R0402 104.648,142.113 r90 top
R26 "0402WGF330JTCE" R0402 85.344,149.225 r270 top
R27 "0402WGF330JTCE" R0402 86.487,149.225 r270 top
R28 "0402WGF330JTCE" R0402 87.63,149.225 r270 top
R29 "0402WGF330JTCE" R0402 88.773,149.225 r270 top
R30 "0402WGF330JTCE" R0402 89.916,149.225 r270 top
R31 "0402WGF330JTCE" R0402 91.059,149.225 r270 top
R32 "0402WGF330JTCE" R0402 92.202,149.225 r270 top
R34 "0402WGF330JTCE" R0402 93.345,149.225 r270 top
R35 "0402WGF1002TCE" R0402 117.094,173.355 r270 top
R36 "0402WGF1002TCE" R0402 136.652,131.953 r90 top
R37 "0402WGF1002TCE" R0402 136.525,126.469 r270 top
R38 "0402WGF1002TCE" R0402 113.665,173.101 r270 top
R39 "0402WGF1002TCE" R0402 115.062,173.228 r270 top
R40 "FRC0603F6202TS" R0603 111.379,88.646 r180 top
R41 "RC0402FR-07130KL" R0402 110.998,90.043 r0 top
R42 "0603WAF5101T5E" R0603 98.552,88.646 r180 top
R43 "0603WAF5101T5E" R0603 98.552,90.17 r180 top
R44 "FRC0603F1963TS" R0603 104.775,95.25 r270 top
R45 "FRC0603F1963TS" R0603 106.807,97.155 r180 top
R46 "FRC0603F6202TS" R0603 120.396,87.63 r0 top
R47 "0402WGF1543TCE" R0402 126.111,86.995 r0 top
R48 "0402WGF330JTCE" R0402 113.157,149.479 r0 bottom
R49 "0402WGF330JTCE" R0402 113.538,146.177 r315 bottom
R50 "0402WGF330JTCE" R0402 113.919,143.129 r315 bottom
R51 "0402WGF330JTCE" R0402 113.157,150.495 r0 bottom
R53 "0402WGF330JTCE" R0402 114.808,152.908 r0 bottom
R54 "0402WGF330JTCE" R0402 112.649,151.765 r0 bottom
R55 "0402WGF330JTCE" R0402 109.855,144.78 r315 top
R56 "0402WGF330JTCE" R0402 111.379,142.113 r315 top
R57 "0402WGF330JTCE" R0402 109.093,143.002 r315 top
R58 "0402WGF330JTCE" R0402 106.553,144.399 r315 top
R59 "0402WGF330JTCE" R0402 108.077,141.478 r315 top
R61 "0402WGF330JTCE" R0402 112.649,161.925 r225 top
R62 "0402WGF330JTCE" R0402 111.76,162.687 r225 top
R63 "0402WGF330JTCE" R0402 109.728,162.306 r225 top
R64 "0402WGF330JTCE" R0402 107.823,161.671 r225 top
R65 "0402WGF330JTCE" R0402 109.093,163.83 r225 top
R66 "0402WGF330JTCE" R0402 106.299,161.925 r225 top
R67 "0402WGF330JTCE" R0402 106.934,164.338 r225 top
R68 "0402WGF330JTCE" R0402 104.394,163.449 r225 top
R69 "0402WGF330JTCE" R0402 115.57,144.907 r315 top
R70 "0402WGF330JTCE" R0402 116.967,160.782 r225 top
R71 "0402WGF330JTCE" R0402 108.331,160.147 r90 bottom
R72 "0402WGF330JTCE" R0402 109.474,160.909 r90 bottom
R73 "0402WGF330JTCE" R0402 109.601,163.195 r90 bottom
R75 "0402WGF330JTCE" R0402 110.49,161.163 r90 bottom
R76 "0402WGF330JTCE" R0402 110.744,163.195 r90 bottom
R77 "0402WGF330JTCE" R0402 111.506,161.544 r90 bottom
R78 "0402WGF330JTCE" R0402 112.649,163.449 r45 bottom
R79 "0402WGF330JTCE" R0402 113.03,162.433 r45 bottom
R80 "0402WGF330JTCE" R0402 114.808,163.703 r45 bottom
R81 "0402WGF330JTCE" R0402 115.316,162.941 r45 bottom
R82 "0402WGF330JTCE" R0402 114.808,161.417 r45 bottom
R83 "0402WGF330JTCE" R0402 116.586,162.306 r45 bottom
R84 "0402WGF330JTCE" R0402 115.824,160.274 r45 bottom
R85 "0402WGF330JTCE" R0402 116.967,159.639 r45 bottom
R86 "0402WGF330JTCE" R0402 101.092,146.304 r270 bottom
R87 "0402WGF330JTCE" R0402 107.569,144.907 r225 bottom
R88 "0402WGF330JTCE" R0402 107.315,148.082 r270 bottom
SCREW1 "Screw-Hole-M2" Screw-Hole-M2 105.664,178.181 r0 top
SCREW2 "Screw-Hole-M3" Screw-Hole-M3 145.442,89.239 r0 top
SCREW3 "Screw-Hole-M3" Screw-Hole-M3 142.494,178.181 r0 top
SCREW4 "Screw-Hole-M3" Screw-Hole-M3 87.672,89.239 r0 top
U1 "LFE5U-25F-6BG256C" CABGA-256_L14.0-W14.0-R16-C16-P0.80-TL 108.077,153.289 r0 top
U2 "ESP32-S3-WROOM-1-N16R2" WIRELM-SMD_ESP32-S3-WROOM-1 101.219,116.586 r90 top
U5 "W9825G6KH-6" TSOP-54_L22.2-W10.2-P0.80-LS11.8-BL 131.318,152.146 r0 top
U6 "AP63200WU-7" SOT-23-6_L2.9-W1.6-P0.95-LS2.8-BR 99.187,102.489 r0 top
U7 "AP63200WU-7" SOT-23-6_L2.9-W1.6-P0.95-LS2.8-BR 120.015,122.682 r180 top
U8 "AMS1117-1.8_C6185" SOT-223-4_L6.5-W3.5-P2.30-LS7.0-BR 119.079,106.709 r0 top
U9 "XOS32024000LT00351005" OSC-SMD_4P-L3.2-W2.5-BL 97.663,145.923 r0 top
U10 "TPS645-5NC60" SW-SMD_4P-L6.0-W6.0-P4.50-LS9.2 142.621,129.286 r0 top
U11 "AP63200WU-7" SOT-23-6_L2.9-W1.6-P0.95-LS2.8-BR 110.416,94.587 r180 top
U12 "AP63200WU-7" SOT-23-6_L2.9-W1.6-P0.95-LS2.8-BR 124.079,91.821 r180 top
USB1 "TYPE-C16PIN" USB-C-SMD_TYPE-C16PIN#1 88.265,96.901 r270 top
USB2 "TYPE-C16PIN" USB-C-SMD_TYPE-C16PIN#2 105.029,89.916 r0 top

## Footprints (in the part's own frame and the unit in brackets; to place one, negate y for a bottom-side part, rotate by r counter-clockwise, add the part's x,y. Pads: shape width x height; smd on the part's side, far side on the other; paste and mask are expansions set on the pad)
C0402 [mm]
  rect 0.79x0.54 smd: 1(-0.545,0) 2(0.545,0)
  silkscreen extent -1.17,-0.5 1.17,0.5
C0603 [mm]
  rect 0.8x0.9 smd: 1(-0.7,0) 2(0.7,0)
  silkscreen extent -1.39,-0.71 1.39,0.71
C0805 [mm]
  rect 1.41x1.35 smd: 1(-1,0) 2(1,0)
  silkscreen extent -1.96,-0.9 1.96,0.9
C01005 [mm]
  rect 0.21x0.22 smd: 1(-0.195,0) 2(0.195,0)
  silkscreen extent -0.46,-0.27 0.46,0.27
CABGA-256_L14.0-W14.0-R16-C16-P0.80-TL [mm]
  round 0.36 smd: A1(-6,6) A2(-5.2,6) A3(-4.4,6) A4(-3.6,6) A5(-2.8,6) A6(-2,6) A7(-1.2,6) A8(-0.4,6) A9(0.4,6) A10(1.2,6) A11(2,6) A12(2.8,6) A13(3.6,6) A14(4.4,6) A15(5.2,6) A16(6,6) B1(-6,5.2) B2(-5.2,5.2) B3(-4.4,5.2) B4(-3.6,5.2) B5(-2.8,5.2) B6(-2,5.2) B7(-1.2,5.2) B8(-0.4,5.2) B9(0.4,5.2) B10(1.2,5.2) B11(2,5.2) B12(2.8,5.2) B13(3.6,5.2) B14(4.4,5.2) B15(5.2,5.2) B16(6,5.2) C1(-6,4.4) C2(-5.2,4.4) C3(-4.4,4.4) C4(-3.6,4.4) C5(-2.8,4.4) C6(-2,4.4) C7(-1.2,4.4) C8(-0.4,4.4) C9(0.4,4.4) C10(1.2,4.4) C11(2,4.4) C12(2.8,4.4) C13(3.6,4.4) C14(4.4,4.4) C15(5.2,4.4) C16(6,4.4) D1(-6,3.6) D2(-5.2,3.6) D3(-4.4,3.6) D4(-3.6,3.6) D5(-2.8,3.6) D6(-2,3.6) D7(-1.2,3.6) D8(-0.4,3.6) D9(0.4,3.6) D10(1.2,3.6) D11(2,3.6) D12(2.8,3.6) D13(3.6,3.6) D14(4.4,3.6) D15(5.2,3.6) D16(6,3.6) E1(-6,2.8) E2(-5.2,2.8) E3(-4.4,2.8) E4(-3.6,2.8) E5(-2.8,2.8) E6(-2,2.8) E7(-1.2,2.8) E8(-0.4,2.8) E9(0.4,2.8) E10(1.2,2.8) E11(2,2.8) E12(2.8,2.8) E13(3.6,2.8) E14(4.4,2.8) E15(5.2,2.8) E16(6,2.8) F1(-6,2) F2(-5.2,2) F3(-4.4,2) F4(-3.6,2) F5(-2.8,2) F6(-2,2) F7(-1.2,2) F8(-0.4,2) F9(0.4,2) F10(1.2,2) F11(2,2) F12(2.8,2) F13(3.6,2) F14(4.4,2) F15(5.2,2) F16(6,2) G1(-6,1.2) G2(-5.2,1.2) G3(-4.4,1.2) G4(-3.6,1.2) G5(-2.8,1.2) G6(-2,1.2) G7(-1.2,1.2) G8(-0.4,1.2) G9(0.4,1.2) G10(1.2,1.2) G11(2,1.2) G12(2.8,1.2) G13(3.6,1.2) G14(4.4,1.2) G15(5.2,1.2) G16(6,1.2) H1(-6,0.4) H2(-5.2,0.4) H3(-4.4,0.4) H4(-3.6,0.4) H5(-2.8,0.4) H6(-2,0.4) H7(-1.2,0.4) H8(-0.4,0.4) H9(0.4,0.4) H10(1.2,0.4) H11(2,0.4) H12(2.8,0.4) H13(3.6,0.4) H14(4.4,0.4) H15(5.2,0.4) H16(6,0.4) J1(-6,-0.4) J2(-5.2,-0.4) J3(-4.4,-0.4) J4(-3.6,-0.4) J5(-2.8,-0.4) J6(-2,-0.4) J7(-1.2,-0.4) J8(-0.4,-0.4) J9(0.4,-0.4) J10(1.2,-0.4) J11(2,-0.4) J12(2.8,-0.4) J13(3.6,-0.4) J14(4.4,-0.4) J15(5.2,-0.4) J16(6,-0.4) K1(-6,-1.2) K2(-5.2,-1.2) K3(-4.4,-1.2) K4(-3.6,-1.2) K5(-2.8,-1.2) K6(-2,-1.2) K7(-1.2,-1.2) K8(-0.4,-1.2) K9(0.4,-1.2) K10(1.2,-1.2) K11(2,-1.2) K12(2.8,-1.2) K13(3.6,-1.2) K14(4.4,-1.2) K15(5.2,-1.2) K16(6,-1.2) L1(-6,-2) L2(-5.2,-2) L3(-4.4,-2) L4(-3.6,-2) L5(-2.8,-2) L6(-2,-2) L7(-1.2,-2) L8(-0.4,-2) L9(0.4,-2) L10(1.2,-2) L11(2,-2) L12(2.8,-2) L13(3.6,-2) L14(4.4,-2) L15(5.2,-2) L16(6,-2) M1(-6,-2.8) M2(-5.2,-2.8) M3(-4.4,-2.8) M4(-3.6,-2.8) M5(-2.8,-2.8) M6(-2,-2.8) M7(-1.2,-2.8) M8(-0.4,-2.8) M9(0.4,-2.8) M10(1.2,-2.8) M11(2,-2.8) M12(2.8,-2.8) M13(3.6,-2.8) M14(4.4,-2.8) M15(5.2,-2.8) M16(6,-2.8) N1(-6,-3.6) N2(-5.2,-3.6) N3(-4.4,-3.6) N4(-3.6,-3.6) N5(-2.8,-3.6) N6(-2,-3.6) N7(-1.2,-3.6) N8(-0.4,-3.6) N9(0.4,-3.6) N10(1.2,-3.6) N11(2,-3.6) N12(2.8,-3.6) N13(3.6,-3.6) N14(4.4,-3.6) N15(5.2,-3.6) N16(6,-3.6) P1(-6,-4.4) P2(-5.2,-4.4) P3(-4.4,-4.4) P4(-3.6,-4.4) P5(-2.8,-4.4) P6(-2,-4.4) P7(-1.2,-4.4) P8(-0.4,-4.4) P9(0.4,-4.4) P10(1.2,-4.4) P11(2,-4.4) P12(2.8,-4.4) P13(3.6,-4.4) P14(4.4,-4.4) P15(5.2,-4.4) P16(6,-4.4) R1(-6,-5.2) R2(-5.2,-5.2) R3(-4.4,-5.2) R4(-3.6,-5.2) R5(-2.8,-5.2) R6(-2,-5.2) R7(-1.2,-5.2) R8(-0.4,-5.2) R9(0.4,-5.2) R10(1.2,-5.2) R11(2,-5.2) R12(2.8,-5.2) R13(3.6,-5.2) R14(4.4,-5.2) R15(5.2,-5.2) R16(6,-5.2) T1(-6,-6) T2(-5.2,-6) T3(-4.4,-6) T4(-3.6,-6) T5(-2.8,-6) T6(-2,-6) T7(-1.2,-6) T8(-0.4,-6) T9(0.4,-6) T10(1.2,-6) T11(2,-6) T12(2.8,-6) T13(3.6,-6) T14(4.4,-6) T15(5.2,-6) T16(6,-6)
  silkscreen extent -7.63,-7.08 7.08,7.3
FPC-SMD_AFC07-S24FCC-00 [mm]
  rect 0.3x1.5 smd: 1(5.745,1.129) 2(5.245,1.129) 3(4.746,1.129) 4(4.245,1.129) 5(3.746,1.129) 6(3.245,1.129) 7(2.746,1.129) 8(2.245,1.129) 9(1.746,1.129) 10(1.245,1.129) 11(0.746,1.129) 12(0.245,1.129) 13(-0.254,1.129) 14(-0.755,1.129) 15(-1.251,1.13) 16(-1.754,1.13) 17(-2.254,1.128) 18(-2.754,1.129) 19(-3.254,1.129) 20(-3.756,1.132) 21(-4.256,1.132) 22(-4.756,1.132) 23(-5.256,1.132) 24(-5.756,1.132)
  rect 2x3 smd: 25(-7.401,-1.132) 26(7.401,-1.125)
  silkscreen extent -8.89,-4.07 8.8,1.61
HDR-TH_6P-P2.54-V-M-1 [mm]
  rect 1.8x1.8 hole 1.2: 1(-6.35,0)
  round 1.8 hole 1.2: 2(-3.81,0) 3(-1.27,0) 4(1.27,0) 5(3.81,0) 6(6.35,0)
  silkscreen extent -7.62,-1.25 7.62,1.25
IND-SMD_L4.5-W4.1_SL0420 [mm]
  rect 1.4x2.3 smd: 1(-1.775,0) 2(1.775,0)
  silkscreen extent -2.03,-2.03 2.03,2.03
IND-SMD_L7.0-W6.6 [mm]
  rect 2.4x3.2 smd: 1(-3,0) 2(3,0)
  silkscreen extent -3.5,-3.3 3.5,3.3
IND-SMD_L7.3-W6.8 [mm]
  rect 2.35x3.5 smd: 1(-3,0) 2(3,0)
  silkscreen extent -3.5,-3.3 3.5,3.3
OSC-SMD_4P-L3.2-W2.5-BL [mm]
  rect 1.4x1.2 smd: 1(-1.1,-0.875) 2(1.1,-0.875) 3(1.1,0.875) 4(-1.1,0.875)
  silkscreen extent -2.29,-1.9 2.07,1.72
R0402 [mm]
  rect 0.566x0.54 smd: 1(-0.433,0) 2(0.433,0)
  silkscreen extent -0.94,-0.5 0.94,0.5
R0603 [mm]
  rect 0.806x0.864 smd: 1(-0.753,0) 2(0.753,0)
  silkscreen extent -1.39,-0.66 1.39,0.66
Screw-Hole-M2 [mm]
  round 2 hole 2: 1(0,0)
  silkscreen extent -1.9,-1.9 1.9,1.9
Screw-Hole-M3 [mil]
  round 126 hole 126: 1(-2.5,2.5)
  silkscreen extent -107,-102 102,107
SOT-23-6_L2.9-W1.6-P0.95-LS2.8-BR [mm]
  rect 1.1x0.6 smd: 1(1.35,-0.95) 2(1.35,0) 3(1.35,0.95) 4(-1.35,0.95) 5(-1.35,0) 6(-1.35,-0.95)
  silkscreen extent -0.9,-1.78 1.52,1.55
SOT-223-4_L6.5-W3.5-P2.30-LS7.0-BR [mm]
  rect 2.47x0.98 smd: 1(2.835,-2.3) 2(2.835,0) 3(2.835,2.3)
  rect 2.47x3.6 smd: 4(-2.835,0)
  silkscreen extent -1.37,-3.33 1.37,3.33
SW-SMD_4P-L6.0-W6.0-P4.50-LS9.2 [mm]
  rect 1.8x1.3 smd: 1(-4.2,2.25) 2(4.2,2.25) 3(-4.2,-2.25) 4(4.2,-2.25)
  silkscreen extent -3,-3 3,3
TF-SMD_DS1139-06-08SS4BSR [mm]
  rect 0.8x2 smd: 1(3.2,-1.6) 2(2.1,-1.6) 3(1,-1.6) 4(-0.1,-1.6) 5(-1.2,-1.6) 6(-2.3,-1.6) 7(-3.4,-1.6) 8(-4.5,-1.6)
  rect 1.8x2.2 smd: 9(-6.8,4.1) 10(-6.8,-4.1) 11(6.8,-4.1) 12(6.8,4.1)
  silkscreen extent -6.8,-6.65 6.8,7.75
TSOP-54_L22.2-W10.2-P0.80-LS11.8-BL [mm]
  oval 0.5x1.8 smd: 1(-10.4,-5.642) 2(-9.6,-5.642) 3(-8.8,-5.642) 4(-8,-5.642) 5(-7.2,-5.642) 6(-6.4,-5.642) 7(-5.6,-5.642) 8(-4.8,-5.642) 9(-4,-5.642) 10(-3.2,-5.642) 11(-2.4,-5.642) 12(-1.6,-5.642) 13(-0.8,-5.642) 14(0,-5.642) 15(0.8,-5.642) 16(1.6,-5.642) 17(2.4,-5.642) 18(3.2,-5.642) 19(4,-5.642) 20(4.8,-5.642) 21(5.6,-5.642) 22(6.4,-5.642) 23(7.2,-5.642) 24(8,-5.642) 25(8.8,-5.642) 26(9.6,-5.642) 27(10.4,-5.642) 28(10.4,5.642) 29(9.6,5.642) 30(8.8,5.642) 31(8,5.642) 32(7.2,5.642) 33(6.4,5.642) 34(5.6,5.642) 35(4.8,5.642) 36(4,5.642) 37(3.2,5.642) 38(2.4,5.642) 39(1.6,5.642) 40(0.8,5.642) 41(0,5.642) 42(-0.8,5.642) 43(-1.6,5.642) 44(-2.4,5.642) 45(-3.2,5.642) 46(-4,5.642) 47(-4.8,5.642) 48(-5.6,5.642) 49(-6.4,5.642) 50(-7.2,5.642) 51(-8,5.642) 52(-8.8,5.642) 53(-9.6,5.642) 54(-10.4,5.642)
  silkscreen extent -11.23,-5.79 11.19,4.65
USB-C-SMD_TYPE-C16PIN#1 [mm]
  oval 1x2.1 hole 0.6 slot 1.7 at 90 deg: 1(-4.32,1.787) 2(4.32,1.787)
  oval 1x1.8 hole 0.6 slot 1.4 at 90 deg: 3(-4.32,-2.362) 4(4.32,-2.362)
  rect 0.6x1.15 smd: A1B12(-3.2,2.362) A4B9(-2.4,2.362) B1A12(3.2,2.362) B4A9(2.4,2.362)
  rect 0.3x1.15 smd: A5(-1.25,2.362) A6(-0.25,2.362) A7(0.25,2.362) A8(1.25,2.362) B5(1.75,2.362) B6(0.75,2.362) B7(-0.75,2.362) B8(-1.75,2.362)
  Board Outline Layer circle w0.005: c2.89,1.288 r0.325
  Board Outline Layer circle w0.005: c-2.89,1.288 r0.325
  Board Outline Layer region: 2.89,1.613 3.031,1.581 3.144,1.491 3.207,1.36 3.207,1.216 3.144,1.085 3.031,0.995 2.89,0.963 2.89,0.963 2.749,0.995 2.636,1.085 2.573,1.216 2.573,1.36 2.636,1.491 2.749,1.581 2.89,1.613
  Board Outline Layer region: -2.89,1.613 -2.749,1.581 -2.636,1.491 -2.573,1.36 -2.573,1.216 -2.636,1.085 -2.749,0.995 -2.89,0.963 -2.89,0.963 -3.031,0.995 -3.144,1.085 -3.207,1.216 -3.207,1.36 -3.144,1.491 -3.031,1.581 -2.89,1.613
  Multi-Layer board cut-out: 2.89,1.613 3.031,1.581 3.144,1.491 3.207,1.36 3.207,1.216 3.144,1.085 3.031,0.995 2.89,0.963 2.89,0.963 2.749,0.995 2.636,1.085 2.573,1.216 2.573,1.36 2.636,1.491 2.749,1.581 2.89,1.613
  Multi-Layer board cut-out: -2.89,1.613 -2.749,1.581 -2.636,1.491 -2.573,1.36 -2.573,1.216 -2.636,1.085 -2.749,0.995 -2.89,0.963 -2.89,0.963 -3.031,0.995 -3.144,1.085 -3.207,1.216 -3.207,1.36 -3.144,1.491 -3.031,1.581 -2.89,1.613
  silkscreen extent -4.45,-5 4.45,0.52
USB-C-SMD_TYPE-C16PIN#2 [mm]
  oval 1x2.1 hole 0.6 slot 1.7 at 90 deg: 1(-4.32,1.787) 2(4.32,1.787)
  oval 1x1.8 hole 0.6 slot 1.4 at 90 deg: 3(-4.32,-2.362) 4(4.32,-2.362)
  rect 0.6x1.15 smd: A1B12(-3.2,2.362) A4B9(-2.4,2.362) B1A12(3.2,2.362) B4A9(2.4,2.362)
  rect 0.3x1.15 smd: A5(-1.25,2.362) A6(-0.25,2.362) A7(0.25,2.362) A8(1.25,2.362) B5(1.75,2.362) B6(0.75,2.362) B7(-0.75,2.362) B8(-1.75,2.362)
  Board Outline Layer circle w0.005: c2.89,1.288 r0.325
  Board Outline Layer circle w0.005: c-2.89,1.288 r0.325
  Board Outline Layer region: 3.215,1.288 3.183,1.147 3.093,1.034 2.962,0.971 2.818,0.971 2.687,1.034 2.597,1.147 2.565,1.288 2.565,1.288 2.597,1.429 2.687,1.542 2.818,1.605 2.962,1.605 3.093,1.542 3.183,1.429 3.215,1.288
  Board Outline Layer region: -2.565,1.288 -2.597,1.147 -2.687,1.034 -2.818,0.971 -2.962,0.971 -3.093,1.034 -3.183,1.147 -3.215,1.288 -3.215,1.288 -3.183,1.429 -3.093,1.542 -2.962,1.605 -2.818,1.605 -2.687,1.542 -2.597,1.429 -2.565,1.288
  Multi-Layer board cut-out: 3.215,1.288 3.183,1.147 3.093,1.034 2.962,0.971 2.818,0.971 2.687,1.034 2.597,1.147 2.565,1.288 2.565,1.288 2.597,1.429 2.687,1.542 2.818,1.605 2.962,1.605 3.093,1.542 3.183,1.429 3.215,1.288
  Multi-Layer board cut-out: -2.565,1.288 -2.597,1.147 -2.687,1.034 -2.818,0.971 -2.962,0.971 -3.093,1.034 -3.183,1.147 -3.215,1.288 -3.215,1.288 -3.183,1.429 -3.093,1.542 -2.962,1.605 -2.818,1.605 -2.687,1.542 -2.597,1.429 -2.565,1.288
  silkscreen extent -4.45,-5 4.45,0.52
WIRELM-SMD_ESP32-S3-WROOM-1 [mm]
  rect 1.5x0.9 smd: 1(-8.75,8.895) 2(-8.75,7.625) 3(-8.75,6.355) 4(-8.75,5.085) 5(-8.75,3.815) 6(-8.75,2.545) 7(-8.75,1.275) 8(-8.75,0.005) 9(-8.75,-1.265) 10(-8.75,-2.535) 11(-8.75,-3.805) 12(-8.75,-5.075) 13(-8.75,-6.345) 14(-8.75,-7.615) 27(8.75,-7.615) 28(8.75,-6.345) 29(8.75,-5.075) 30(8.75,-3.805) 31(8.75,-2.535) 32(8.75,-1.265) 33(8.75,0.005) 34(8.75,1.275) 35(8.75,2.545) 36(8.75,3.815) 37(8.75,5.085) 38(8.75,6.355) 39(8.75,7.625) 40(8.75,8.895)
  rect 0.9x1.5 smd: 15(-6.985,-8.895) 16(-5.715,-8.895) 17(-4.445,-8.895) 18(-3.175,-8.895) 19(-1.905,-8.895) 20(-0.635,-8.895) 21(0.635,-8.895) 22(1.905,-8.895) 23(3.175,-8.895) 24(4.445,-8.895) 25(5.715,-8.895) 26(6.985,-8.865)
  rect 0.9x0.9 smd: 41(-2.9,-0.225) 41(-2.9,1.175) 41(-2.9,2.575) 41(-1.5,2.575) 41(-1.5,-0.225) 41(-1.5,1.175) 41(-0.1,2.575) 41(-0.1,1.175) 41(-0.1,-0.225)
  silkscreen extent -9,-9.14 9.02,16.39

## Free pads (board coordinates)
  round 1.524 hole 0.914: 1(96.52,104.267) 1(107.442,127.381)
  round 0.08 smd: 55(92.324,127.195) 55(93.345,126.873) 55(94.234,96.647) 55(94.234,126.492) 55(96.266,92.202) 55(121.914,103.597) 55(123.394,105.627)
  round 0.08 smd far side: 55(102.235,127.254) 55(108.839,136.377) 55(110.617,137.16)

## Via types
v1: diameter 0.4, hole 0.3, Top Layer to Bottom Layer, 448 vias
v2: diameter 1, hole 0.5, Top Layer to Bottom Layer, 28 vias
v3: diameter 0.5, hole 0.3, Top Layer to Bottom Layer, 1 vias

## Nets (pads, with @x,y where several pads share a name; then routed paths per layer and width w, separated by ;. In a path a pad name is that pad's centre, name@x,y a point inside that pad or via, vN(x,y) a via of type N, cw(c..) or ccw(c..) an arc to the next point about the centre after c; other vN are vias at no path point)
$1N9437: R1.1 U5.37 | length 2.5
  Top Layer w0.254: R1.1@133.731,159.968 134.518,159.181 U5.37@134.518,157.788
$1N11348: R2.1 U5.38 | length 21
  Top Layer w0.1: R2.1@116.892,153.289 133.096,153.289 133.718,153.911 U5.38@133.718,157.788
$1N11975: R7.1 U2.3 | length 1.5
  Top Layer w0.254: U2.3@94.991,107.836 94.996,107.831 R7.1@94.996,106.351
$1N12553: R10.2 USB1.B5 | length 2.6
  Top Layer w0.1: USB1.B5@90.627,95.151 91.138,95.151 91.957,95.97 R10.2@91.957,96.901
$1N12557: R9.2 USB1.A5 | length 3.6
  Top Layer w0.1: USB1.A5@90.627,98.151 93.316,98.151 R9.2@93.98,98.815
$1N14416: C18.2 L1.1 U6.5 | length 7.6
  Top Layer w0.254: L1.1@96.187,96.901 96.187,99.06 95.758,99.489 95.758,102.141 96.04,102.424 96.26,102.424 C18.2@96.266,102.43 97.778,102.43 U6.5@97.837,102.489
$1N14459: C18.1 U6.6 | length 1.8
  Top Layer w0.254: C18.1@96.266,102.04 96.767,101.539 U6.6@97.837,101.539
$1N14567: C19.1 R11.1 R12.2 U6.1 | length 11.6
  Top Layer w0.254: U6.1@100.537,101.539 104.52,101.539 C19.1@105.664,100.395 108.659,100.395 R11.1@108.712,100.448 111.616,100.448 R12.2@111.633,100.466
$1N16832: C24.2 L2.1 U7.5 | length 7.6
  Top Layer w0.6: U7.5@121.365,122.682 123.19,122.682 124.031,123.523 124.031,127.889 L2.1@123.904,128.016
$1N16833: C24.1 U7.6 | length 1
  Top Layer w0.6: U7.6@121.365,123.632 121.927,123.632 122.134,123.425 122.301,123.425
$1N16834: C25.1 R14.2 R15.1 U7.1 | length 5.4
  Top Layer w0.4: C25.1@116.524,125.222 116.704,125.042 R15.1@116.704,123.444 ; R14.2@116.704,121.92 R15.1@116.704,123.444 ; U7.1@118.665,123.632 118.477,123.444 R15.1@116.704,123.444
$1N17349: C29.2 C30.2 C31.1 C32.1 | length 3.8
  Top Layer w0.254: C30.2@124.274,109.093 125.349,108.018 C32.1@125.349,106.717 124.438,106.717 C29.2@124.401,106.68
$1N29790: R26.2 U2.5 | length 58.5
  Top Layer w0.1: v1(85.082,147.955) 85.344,148.217 R26.2@85.344,148.792 ; U2.5@97.531,107.836 97.536,107.831 v1(97.536,106.807)
  Bottom Layer w0.1: v1(85.082,147.955) 85.471,147.566 85.471,106.934 86.741,105.664 87.041,105.664 87.112,105.735 87.112,105.974 87.182,106.045 87.441,106.045 87.512,105.974 87.512,105.735 87.582,105.664 87.841,105.664 87.912,105.735 87.912,105.974 87.982,106.045 88.241,106.045 88.312,105.974 88.312,105.735 88.382,105.664 88.641,105.664 88.712,105.735 88.712,105.974 88.782,106.045 89.041,106.045 89.112,105.974 89.112,105.735 89.182,105.664 89.441,105.664 89.512,105.735 89.512,105.904 89.582,105.974 89.841,105.974 89.912,105.904 89.912,105.735 89.982,105.664 94.995,105.664 96.138,106.807 v1(97.536,106.807)
$1N29833: R27.2 U2.6 | length 59.5
  Top Layer w0.1: v1(85.761,147.919) 85.761,148.066 R27.2@86.487,148.792 ; v1(98.801,106.807) U2.6@98.801,107.836
  Bottom Layer w0.1: v1(85.761,147.919) 85.761,109.057 87.249,107.569 87.947,107.569 88.018,107.64 88.018,108.133 88.089,108.204 88.347,108.204 88.418,108.133 88.418,107.64 88.489,107.569 88.747,107.569 88.818,107.64 88.818,108.133 88.889,108.204 89.147,108.204 89.218,108.133 89.218,107.64 89.289,107.569 89.547,107.569 89.618,107.64 89.618,108.133 89.689,108.204 89.947,108.204 90.018,108.133 90.018,107.64 90.089,107.569 90.347,107.569 90.418,107.64 90.418,108.133 90.489,108.204 90.747,108.204 90.818,108.133 90.818,107.64 90.889,107.569 98.039,107.569 v1(98.801,106.807)
$1N29916: R29.2 U2.9 | length 59.1
  Top Layer w0.1: v1(87.072,147.751) 87.427,147.751 88.469,148.792 R29.2@88.773,148.792 ; v1(101.219,109.601) 102.611,108.209 U2.9@102.611,107.836
  Bottom Layer w0.1: v1(87.072,147.751) 86.87,147.549 86.814,147.549 86.541,147.276 86.541,146.979 86.612,146.909 86.797,146.909 86.868,146.838 86.868,146.579 86.797,146.509 86.612,146.509 86.541,146.438 86.541,146.179 86.612,146.109 86.797,146.109 86.868,146.038 86.868,145.779 86.797,145.709 86.612,145.709 86.541,145.638 86.541,145.379 86.612,145.309 86.797,145.309 86.868,145.238 86.868,144.979 86.797,144.909 86.612,144.909 86.541,144.838 86.541,144.579 86.612,144.509 86.797,144.509 86.868,144.438 86.868,144.179 86.797,144.109 86.612,144.109 86.541,144.038 86.541,143.779 86.612,143.709 86.797,143.709 86.868,143.638 86.868,143.379 86.797,143.309 86.612,143.309 86.541,143.238 86.541,143.024 86.612,142.954 86.797,142.954 86.868,142.883 86.868,142.624 86.797,142.554 86.612,142.554 86.541,142.483 86.541,142.224 86.612,142.154 86.797,142.154 86.868,142.083 86.868,141.824 86.797,141.754 86.612,141.754 86.541,141.683 86.541,112.849 89.789,109.601 v1(101.219,109.601)
$1N29959: R30.2 U2.12 | length 59
  Top Layer w0.1: v1(88.011,147.701) 88.825,147.701 R30.2@89.916,148.792 ; v1(98.552,111.125) 104.521,111.125 106.421,109.225 U2.12@106.421,107.836
  Bottom Layer w0.1: v1(88.011,147.701) 87.591,147.701 87.239,147.349 87.239,147.339 87.195,147.295 87.195,114.354 90.424,111.125 v1(98.552,111.125)
$1N30002: R31.2 U2.23 | length 58.9
  Top Layer w0.1: v1(88.392,120.777) 108.204,120.777 109.22,119.761 U2.23@110.114,119.761 ; v1@89.281,147.701 89.968,147.701 R31.2@91.059,148.792
  Bottom Layer w0.1: v1(88.392,120.777) 87.796,121.373 87.796,136.711 87.725,136.782 87.495,136.782 87.424,136.852 87.424,137.111 87.495,137.182 87.725,137.182 87.796,137.252 87.796,137.511 87.725,137.582 87.495,137.582 87.424,137.652 87.424,137.911 87.495,137.982 87.725,137.982 87.796,138.052 87.796,138.311 87.725,138.382 87.495,138.382 87.424,138.452 87.424,138.711 87.495,138.782 87.725,138.782 87.796,138.852 87.796,139.111 87.725,139.182 87.495,139.182 87.424,139.252 87.424,139.511 87.495,139.582 87.725,139.582 87.796,139.652 87.796,139.911 87.725,139.982 87.495,139.982 87.424,140.052 87.424,140.311 87.495,140.382 87.725,140.382 87.796,140.452 87.796,140.711 87.725,140.782 87.495,140.782 87.424,140.852 87.424,141.111 87.495,141.182 87.725,141.182 87.796,141.252 87.796,141.511 87.725,141.582 87.495,141.582 87.424,141.652 87.424,141.911 87.495,141.982 87.725,141.982 87.796,142.052 87.796,142.311 87.725,142.382 87.495,142.382 87.424,142.452 87.424,142.711 87.495,142.782 87.725,142.782 87.796,142.852 87.796,143.111 87.725,143.182 87.495,143.182 87.424,143.252 87.424,143.511 87.495,143.582 87.725,143.582 87.796,143.652 87.796,143.911 87.725,143.982 87.495,143.982 87.424,144.052 87.424,144.311 87.495,144.382 87.725,144.382 87.796,144.452 87.796,145.249 87.395,145.65 87.395,146.933 87.674,147.212 88.523,147.212 88.956,147.645 v1(89.337,147.645)
$1N30085: R34.2 U2.25 | length 59.1
  Top Layer w0.1: v1@91.44,147.447 92.127,147.447 93.345,148.665 R34.2@93.345,148.792 ; v1(91.948,122.428) 92.075,122.301 92.883,122.301 92.954,122.372 92.954,122.611 93.025,122.682 93.283,122.682 93.354,122.611 93.354,122.372 93.425,122.301 93.683,122.301 93.754,122.372 93.754,122.611 93.825,122.682 94.083,122.682 94.154,122.611 94.154,122.372 94.225,122.301 94.483,122.301 94.554,122.372 94.554,122.611 94.625,122.682 94.883,122.682 94.954,122.611 94.954,122.372 95.025,122.301 95.283,122.301 95.354,122.372 95.354,122.611 95.425,122.682 95.683,122.682 95.754,122.611 95.754,122.372 95.825,122.301 96.083,122.301 96.154,122.372 96.154,122.611 96.225,122.682 96.483,122.682 96.554,122.611 96.554,122.372 96.625,122.301 U2.25@110.114,122.301
  Bottom Layer w0.1: v1(91.433,147.454) 89.408,145.43 89.408,145.109 89.479,145.038 89.845,145.038 89.916,144.968 89.916,144.709 89.845,144.638 89.479,144.638 89.408,144.568 89.408,144.309 89.479,144.238 89.835,144.238 89.906,144.168 89.906,143.909 89.835,143.838 89.479,143.838 89.408,143.768 89.408,143.509 89.479,143.438 89.844,143.438 89.915,143.368 89.915,143.109 89.844,143.038 89.479,143.038 89.408,142.968 89.408,142.709 89.479,142.638 89.835,142.638 89.906,142.568 89.906,142.309 89.835,142.238 89.479,142.238 89.408,142.168 89.408,141.909 89.479,141.838 89.88,141.838 89.95,141.768 89.95,141.509 89.88,141.438 89.479,141.438 89.408,141.368 89.408,141.109 89.479,141.038 89.907,141.038 89.977,140.968 89.977,140.709 89.907,140.638 89.479,140.638 89.408,140.568 89.408,140.309 89.479,140.238 89.952,140.238 90.022,140.168 90.022,139.909 89.952,139.838 89.479,139.838 89.408,139.768 89.408,139.554 89.479,139.483 89.887,139.483 89.958,139.412 89.958,139.154 89.887,139.083 89.479,139.083 89.408,139.012 89.408,138.754 89.479,138.683 89.887,138.683 89.958,138.612 89.958,138.354 89.887,138.283 89.479,138.283 89.1,137.904 89.1,125.276 v1(91.948,122.428)
$1N30089: R32.2 U2.24 | length 59
  Top Layer w0.1: v1(90.424,147.574) 90.984,147.574 R32.2@92.202,148.792 ; v1(91.694,121.793) 108.077,121.793 108.839,121.031 U2.24@110.114,121.031
  Bottom Layer w0.1: v1(90.424,147.574) 89.862,147.012 88.861,147.012 88.265,146.416 88.265,144.684 88.336,144.614 88.829,144.614 88.9,144.543 88.9,144.284 88.829,144.214 88.336,144.214 88.265,144.143 88.265,143.884 88.336,143.814 88.829,143.814 88.9,143.743 88.9,143.484 88.829,143.414 88.336,143.414 88.265,143.343 88.265,143.084 88.336,143.014 88.829,143.014 88.9,142.943 88.9,142.684 88.829,142.614 88.336,142.614 88.265,142.543 88.265,142.284 88.336,142.214 88.829,142.214 88.9,142.143 88.9,141.884 88.829,141.814 88.336,141.814 88.265,141.743 88.265,141.484 88.336,141.414 88.829,141.414 88.9,141.343 88.9,141.084 88.829,141.014 88.336,141.014 88.265,140.943 88.265,140.684 88.336,140.614 88.829,140.614 88.9,140.543 88.9,140.284 88.829,140.214 88.336,140.214 88.265,140.143 88.265,139.884 88.336,139.814 88.829,139.814 88.9,139.743 88.9,139.484 88.829,139.414 88.336,139.414 88.265,139.343 88.265,139.084 88.336,139.014 88.829,139.014 88.9,138.943 88.9,138.684 88.829,138.614 88.336,138.614 88.265,138.543 88.265,138.284 88.336,138.214 88.531,138.214 88.602,138.143 88.602,137.884 88.531,137.814 88.336,137.814 88.265,137.743 88.265,125.222 v1(91.694,121.793)
$1N30093: R28.2 U2.7 | length 59.7
  Top Layer w0.1: v1(86.393,147.828) 86.454,147.828 87.419,148.792 R28.2@87.63,148.792 ; U2.7@100.071,107.836 v1(100.071,108.839)
  Bottom Layer w0.1: v1(86.393,147.828) 86.106,147.541 86.106,109.728 86.995,108.839 88.99,108.839 89.061,108.91 89.061,109.022 89.132,109.093 89.39,109.093 89.461,109.022 89.461,108.91 89.532,108.839 90.237,108.839 90.308,108.91 90.308,109.265 90.379,109.336 90.637,109.336 90.708,109.265 90.708,108.91 90.779,108.839 91.037,108.839 91.108,108.91 91.108,109.265 91.179,109.336 91.437,109.336 91.508,109.265 91.508,108.91 91.579,108.839 91.837,108.839 91.908,108.91 91.908,109.265 91.979,109.336 92.237,109.336 92.308,109.265 92.308,108.91 92.379,108.839 92.637,108.839 92.708,108.91 92.708,109.265 92.779,109.336 93.037,109.336 93.108,109.265 93.108,108.91 93.179,108.839 93.437,108.839 93.508,108.91 93.508,109.265 93.579,109.336 93.837,109.336 93.908,109.265 93.908,108.91 93.979,108.839 v1(100.071,108.839)
$1N60668: C64.1 U11.6 | length 1.6
  Top Layer w0.5: U11.6@111.766,95.537 111.766,95.844 112.499,96.578 112.776,96.578
$1N60669: C64.2 L3.1 U11.5 | length 3.6
  Top Layer w0.1: L3.1@113.442,94.587 L3.1@113.541,94.488
  Top Layer w0.5: U11.5@111.766,94.587 L3.1@113.442,94.587 ; 112.821,95.954 113.541,95.234 L3.1@113.541,94.488
$1N60670: C65.1 R40.2 R41.1 U11.1 | length 8
  Top Layer w0.1: U11.1@109.066,95.537 109.822,95.537 110.626,94.733 R40.2@110.626,88.646
$1N63749: R43.1 USB2.A5 | length 6.1
  Top Layer w0.1: R43.1@99.305,90.17 99.432,90.043 v1(100.203,90.043) ; v1(103.779,91.186) USB2.A5@103.779,92.278
  Bottom Layer w0.1: v1(100.203,90.043) 102.636,90.043 v1(103.779,91.186)
$1N63772: R42.1 USB2.B5 | length 10.5
  Top Layer w0.1: R42.1@99.305,88.646 100.076,88.646 v1(100.203,88.773) ; USB2.B5@106.779,92.278 106.807,92.251 v1(106.807,91.313)
  Bottom Layer w0.1: v1(100.203,88.773) 100.965,89.535 106.553,89.535 106.581,89.563 106.581,91.087 v1(106.807,91.313)
$1N63825: R44.2 USB2.A4B9 USB2.B4A9 | length 12.3
  Top Layer w0.1: USB2.A4B9@102.629,92.278 102.87,92.037 v1(102.87,91.059) 103.309,90.62 107.13,90.62 107.392,90.882 107.392,92.241 USB2.B4A9@107.429,92.278 ; v1(103.759,94.361) 104.639,94.361 R44.2@104.775,94.497
  Bottom Layer w0.1: v1(102.87,91.059) 102.87,93.472 v1(103.759,94.361)
$1N64401: C69.2 L4.1 U12.5 | length 3.6
  Top Layer w0.4: C69.2@126.373,93.599 127.003,92.969 L4.1@127.003,91.821
  Top Layer w0.5: U12.5@125.429,91.821 L4.1@127.003,91.821
$1N64402: C69.1 U12.6 | length 1
  Top Layer w0.4: U12.6@125.429,92.771 125.429,93.179 C69.1@125.849,93.599
$1N64403: C70.1 R46.2 R47.1 U12.1 | length 10.6
  Top Layer w0.1: R46.2@121.149,87.63 122.617,87.63 C70.1@122.744,87.757 ; U12.1@122.729,92.771 122.79,92.71 122.976,92.71 123.481,92.205 123.481,90.487 122.744,89.75 C70.1@122.744,87.757 ; R47.1@125.678,86.995 123.506,86.995 C70.1@122.744,87.757
$1N71242: R48.2 U5.16 | length 44.9
  Top Layer w0.254: v1(132.918,145.288) U5.16@132.918,146.504
  Bottom Layer w0.1: R48.2@113.522,149.352 113.593,149.281 113.593,148.661 113.664,148.59 113.922,148.59 113.993,148.661 113.993,149.281 114.064,149.352 114.322,149.352 114.393,149.281 114.393,148.661 114.464,148.59 114.722,148.59 114.793,148.661 114.793,149.281 114.864,149.352 115.122,149.352 115.193,149.281 115.193,148.661 115.264,148.59 115.522,148.59 115.593,148.661 115.593,149.281 115.664,149.352 115.922,149.352 115.993,149.281 115.993,148.661 116.064,148.59 116.322,148.59 116.393,148.661 116.393,149.281 116.464,149.352 116.722,149.352 116.793,149.281 116.793,148.661 116.864,148.59 117.122,148.59 117.193,148.661 117.193,149.281 117.264,149.352 117.522,149.352 117.593,149.281 117.593,148.661 117.664,148.59 117.922,148.59 117.993,148.661 117.993,149.281 118.064,149.352 118.322,149.352 118.393,149.281 118.393,148.661 118.464,148.59 118.722,148.59 118.793,148.661 118.793,149.281 118.864,149.352 119.122,149.352 119.193,149.281 119.193,148.661 119.264,148.59 119.522,148.59 119.593,148.661 119.593,149.281 119.664,149.352 119.922,149.352 119.993,149.281 119.993,148.661 120.064,148.59 120.322,148.59 120.393,148.661 120.393,149.281 120.464,149.352 120.722,149.352 120.793,149.281 120.793,148.661 120.864,148.59 121.122,148.59 121.193,148.661 121.193,149.281 121.264,149.352 121.522,149.352 121.593,149.281 121.593,148.661 121.664,148.59 121.922,148.59 121.993,148.661 121.993,149.281 122.064,149.352 122.322,149.352 122.393,149.281 122.393,148.661 122.464,148.59 122.722,148.59 122.793,148.661 122.793,149.281 122.864,149.352 123.122,149.352 123.193,149.281 123.193,148.661 123.264,148.59 123.522,148.59 123.593,148.661 123.593,149.281 123.664,149.352 123.922,149.352 123.993,149.281 123.993,148.661 124.064,148.59 124.322,148.59 124.393,148.661 124.393,149.281 124.464,149.352 124.901,149.352 124.972,149.281 124.972,149.169 125.043,149.098 125.301,149.098 125.372,149.169 125.372,149.281 125.443,149.352 125.701,149.352 125.772,149.281 125.772,149.169 125.843,149.098 126.101,149.098 126.172,149.169 126.172,149.281 126.243,149.352 126.501,149.352 126.572,149.281 126.572,149.169 126.643,149.098 126.901,149.098 126.972,149.169 126.972,149.281 127.043,149.352 128.854,149.352 130.554,147.652 130.554,147.552 130.298,147.297 130.298,147.197 130.481,147.014 130.581,147.014 130.837,147.269 130.937,147.269 131.119,147.086 131.119,146.986 130.864,146.731 130.864,146.631 131.047,146.448 131.147,146.448 131.402,146.704 131.502,146.704 131.685,146.521 131.685,146.421 131.43,146.165 131.43,146.065 131.613,145.882 131.713,145.882 131.968,146.138 132.068,146.138 v1(132.918,145.288)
